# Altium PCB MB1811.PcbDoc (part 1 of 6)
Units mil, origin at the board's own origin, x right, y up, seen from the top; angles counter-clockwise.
Board outline 3480.3 x 4291.34 mil, 4 copper layers (Top Layer, L2_VCC, L3_GND, Bottom Layer), stack 30.59 mil thick; 371 components, 285 nets, 1369 pads, 606 vias.
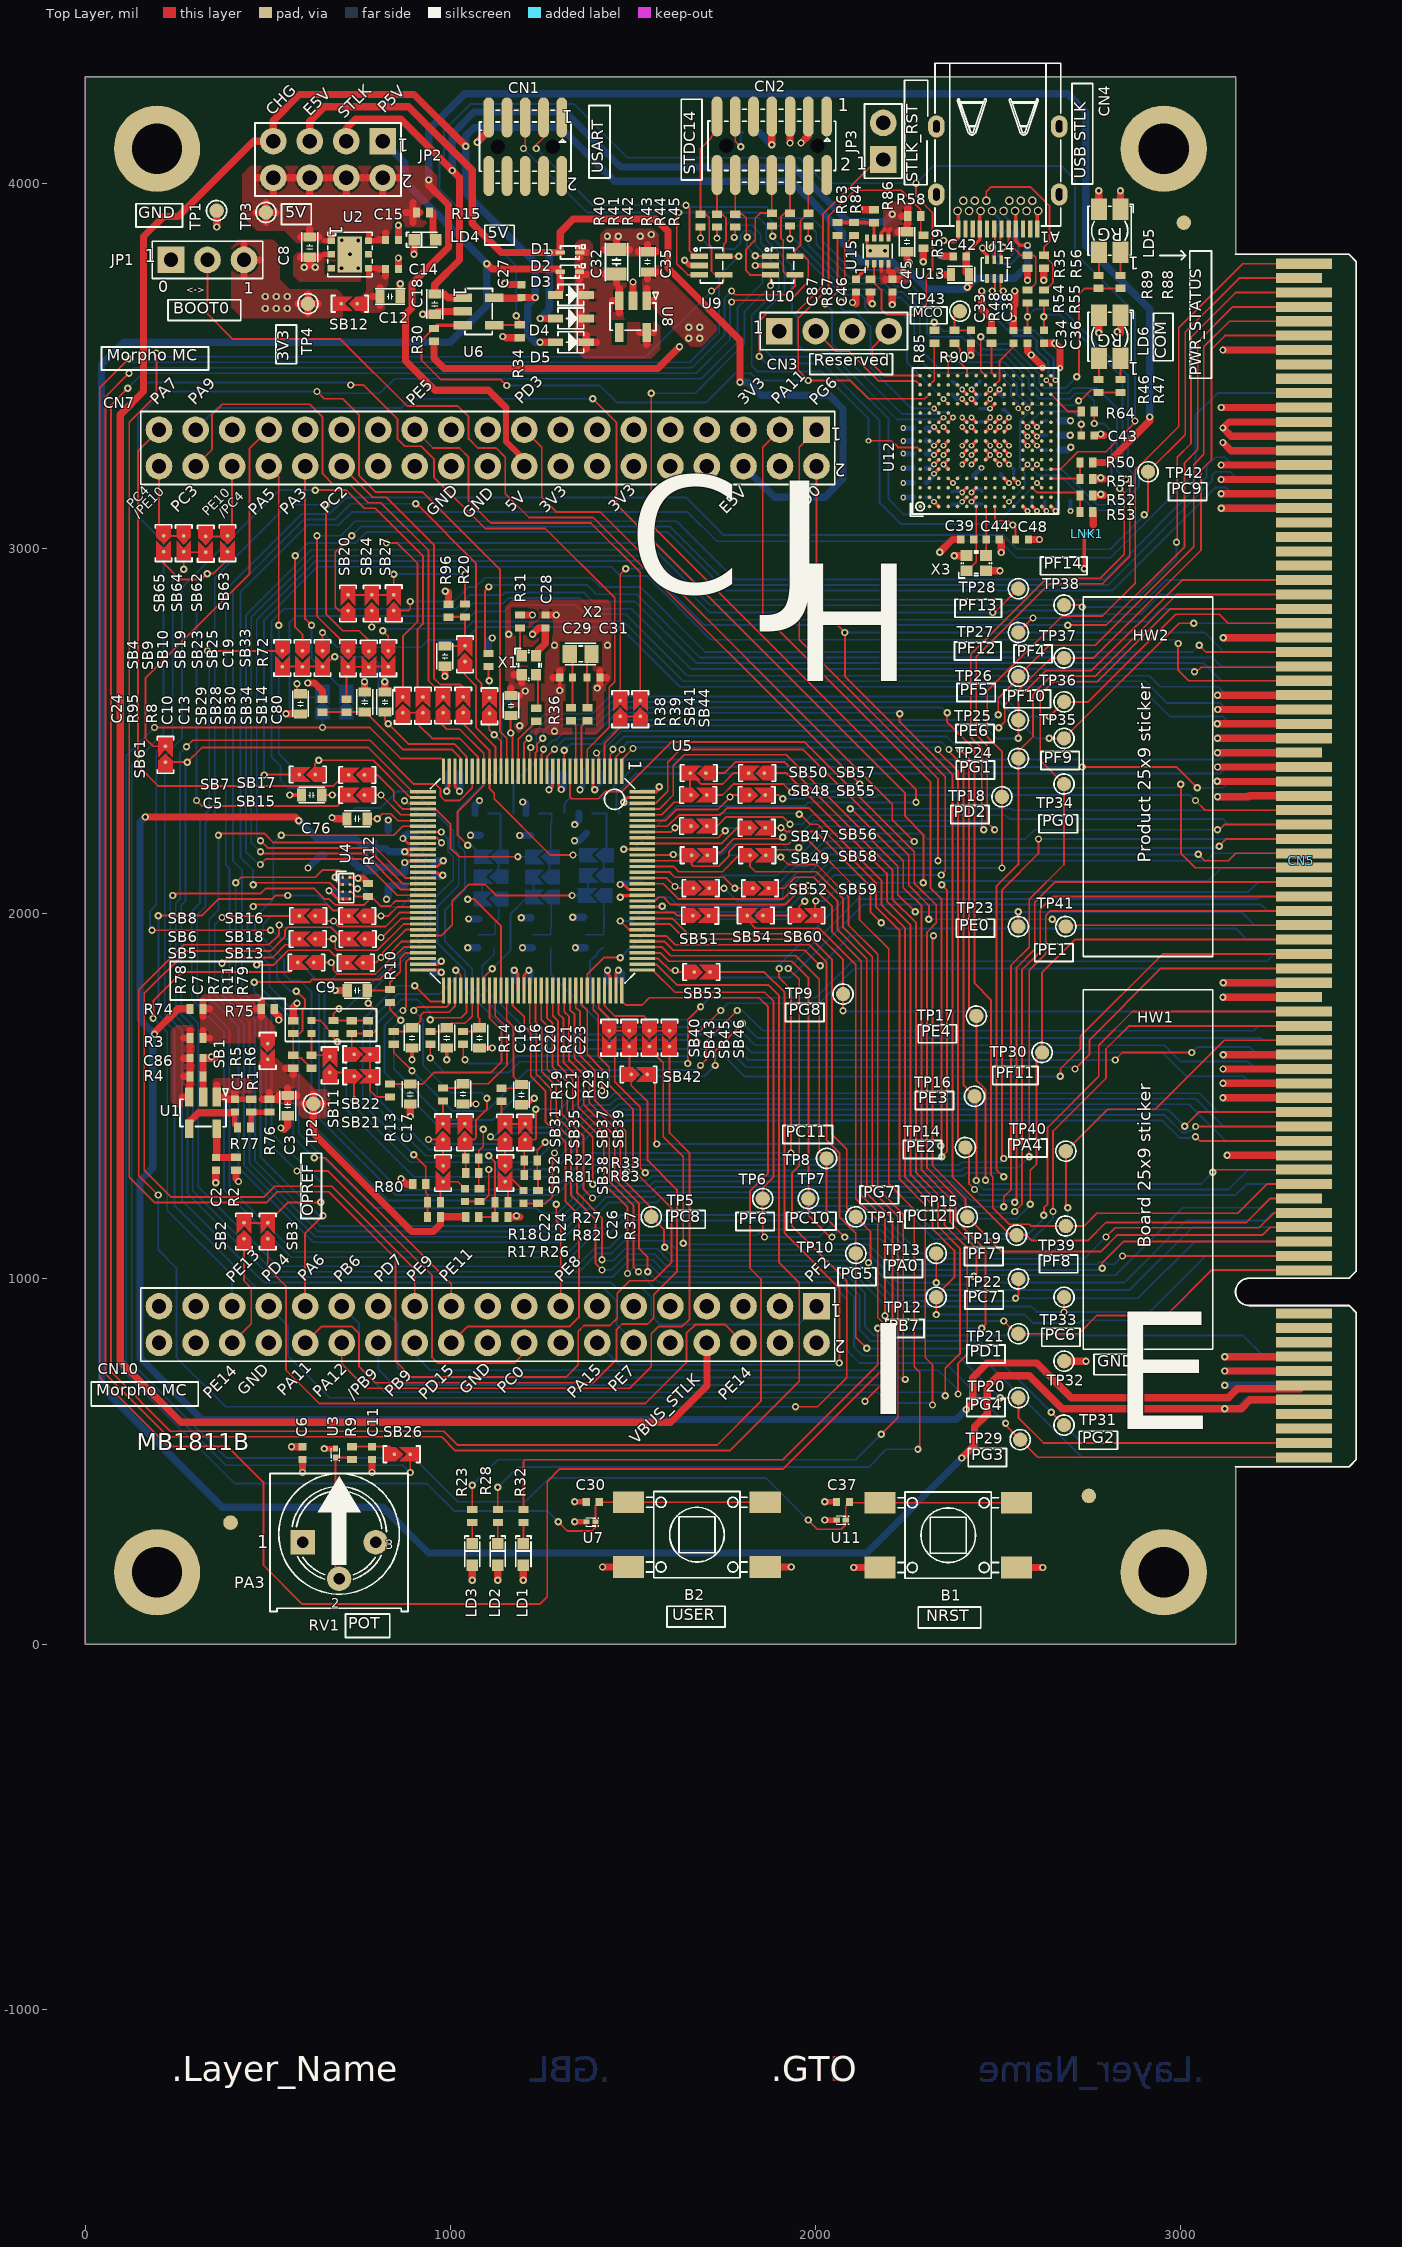
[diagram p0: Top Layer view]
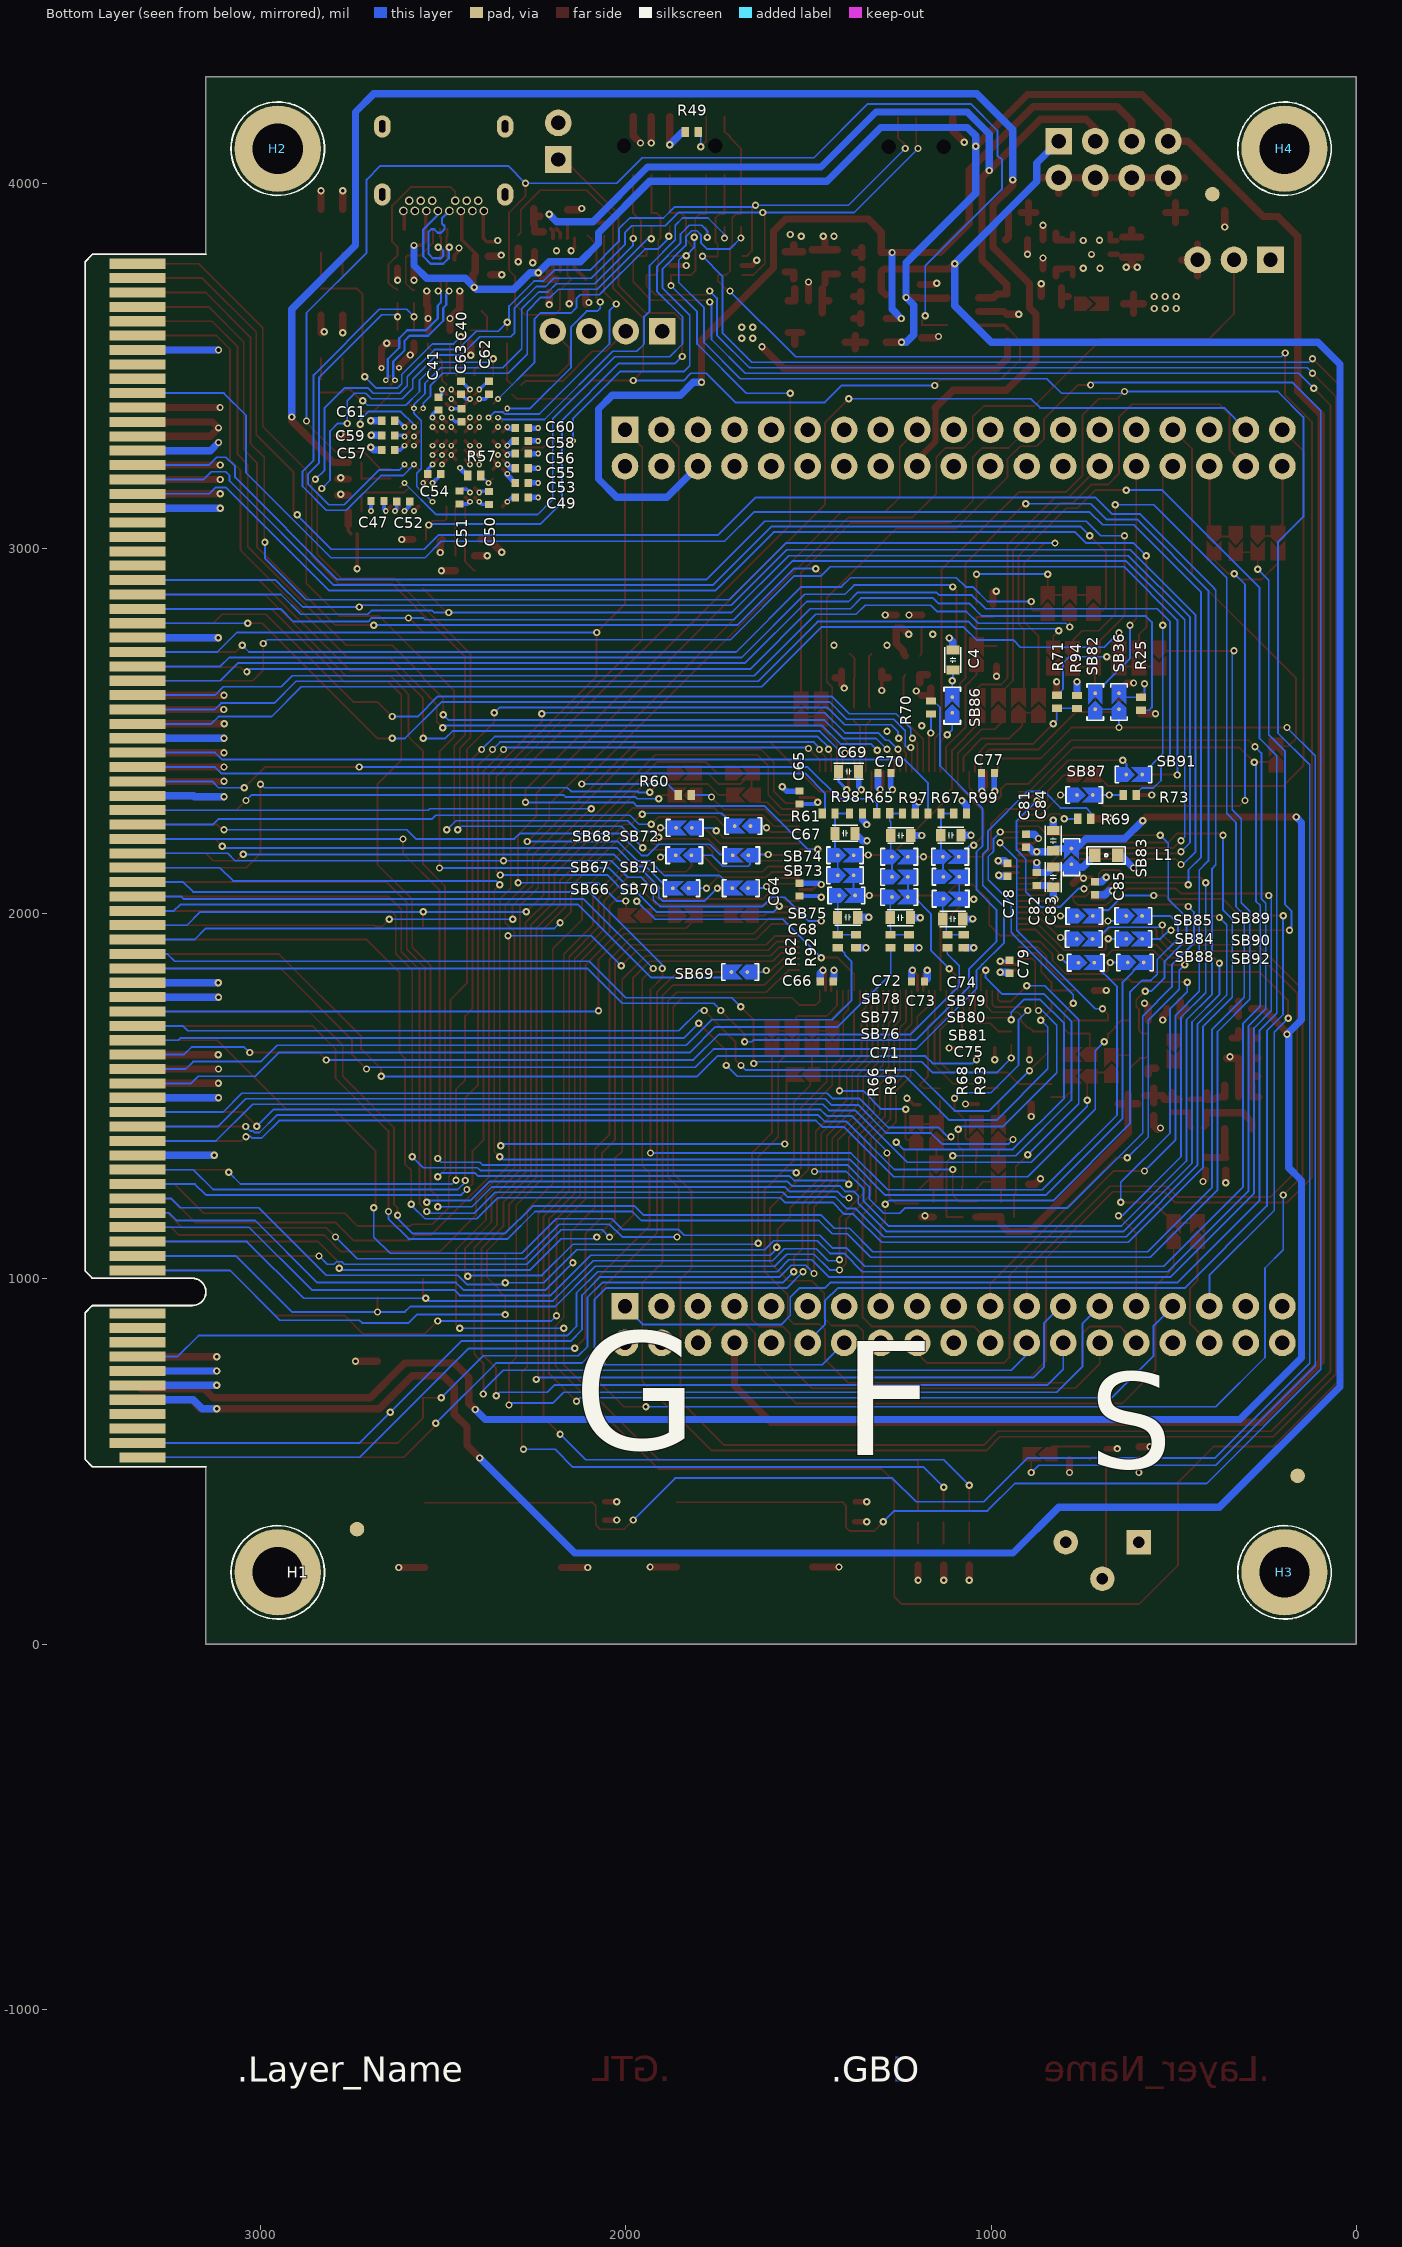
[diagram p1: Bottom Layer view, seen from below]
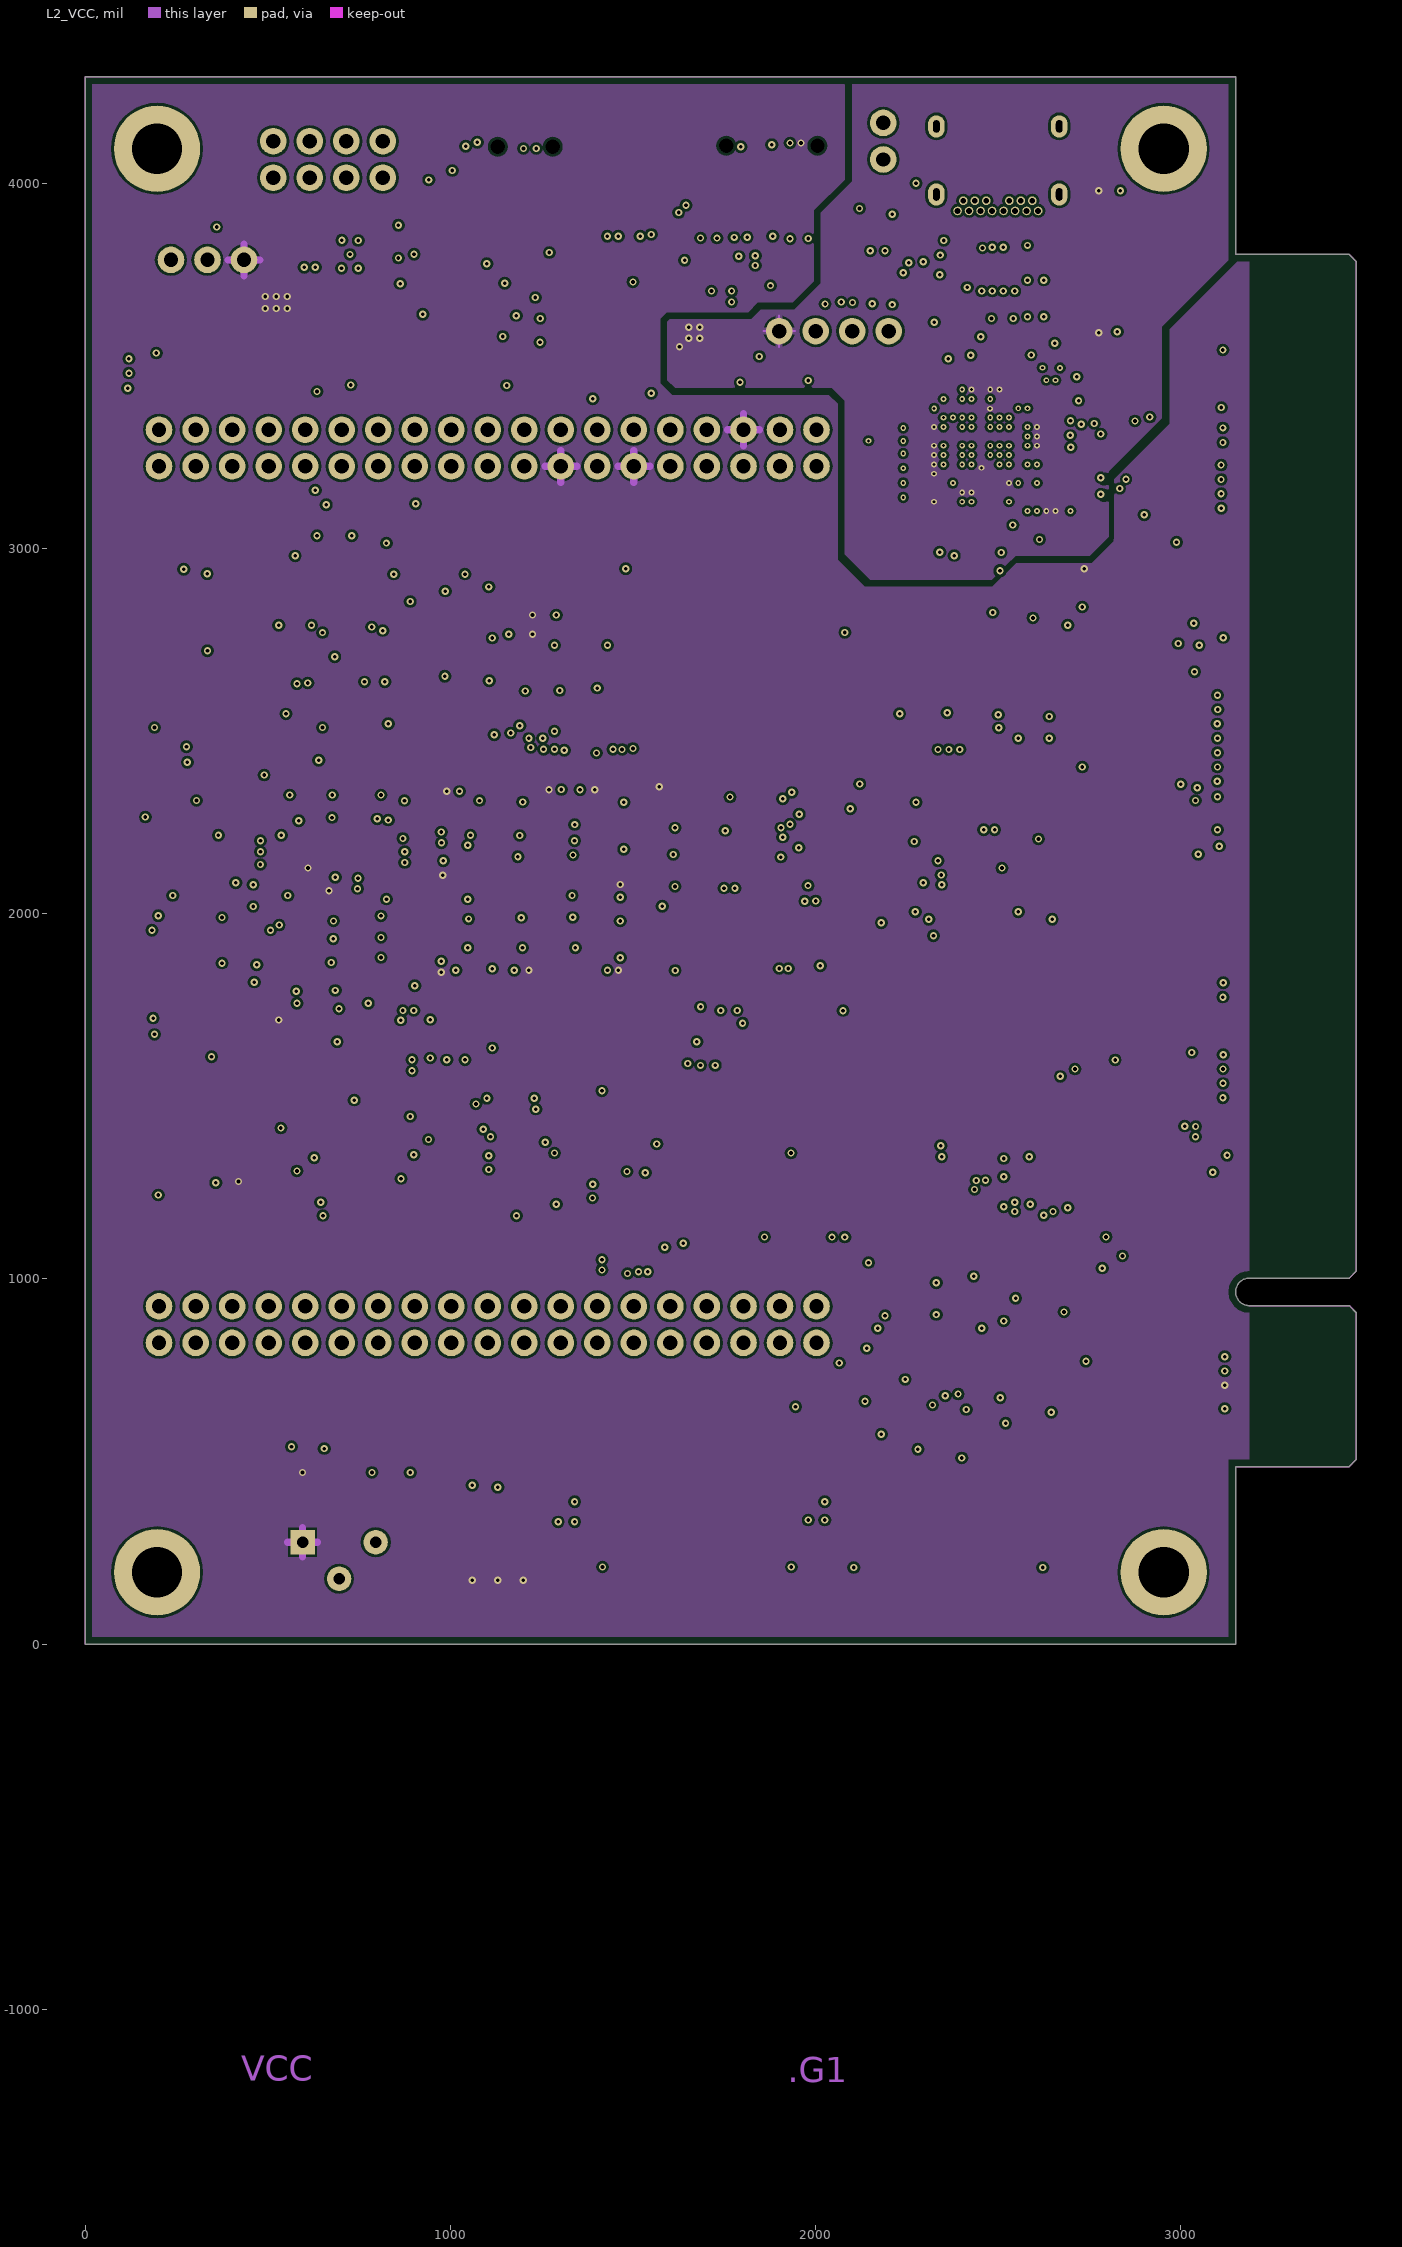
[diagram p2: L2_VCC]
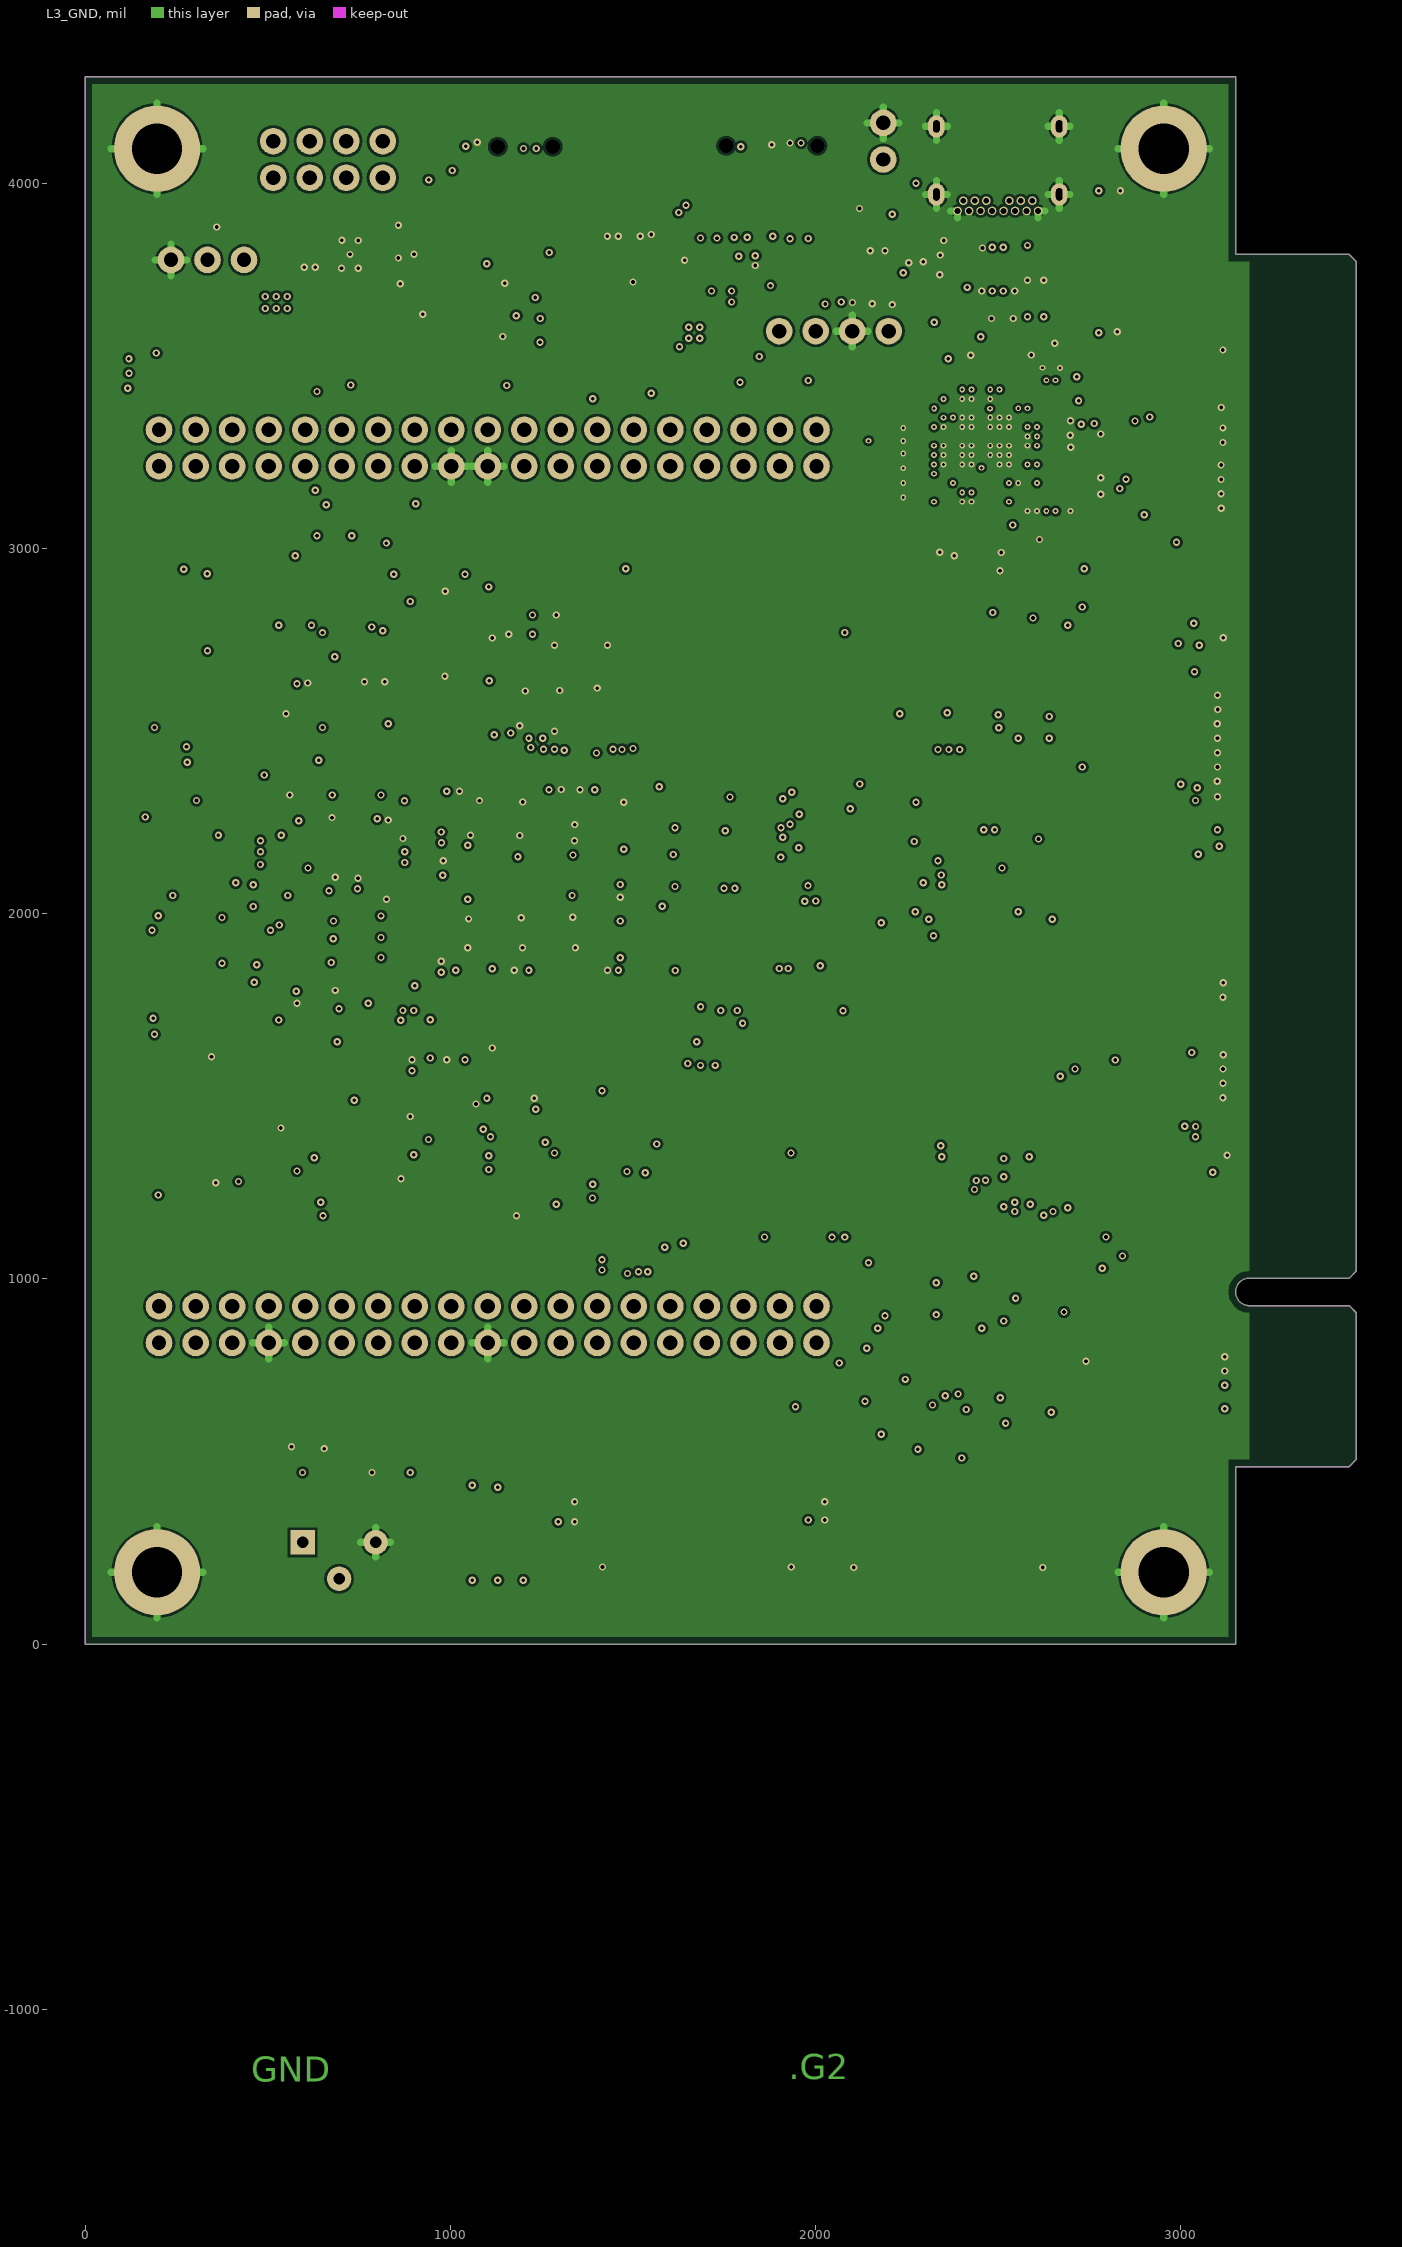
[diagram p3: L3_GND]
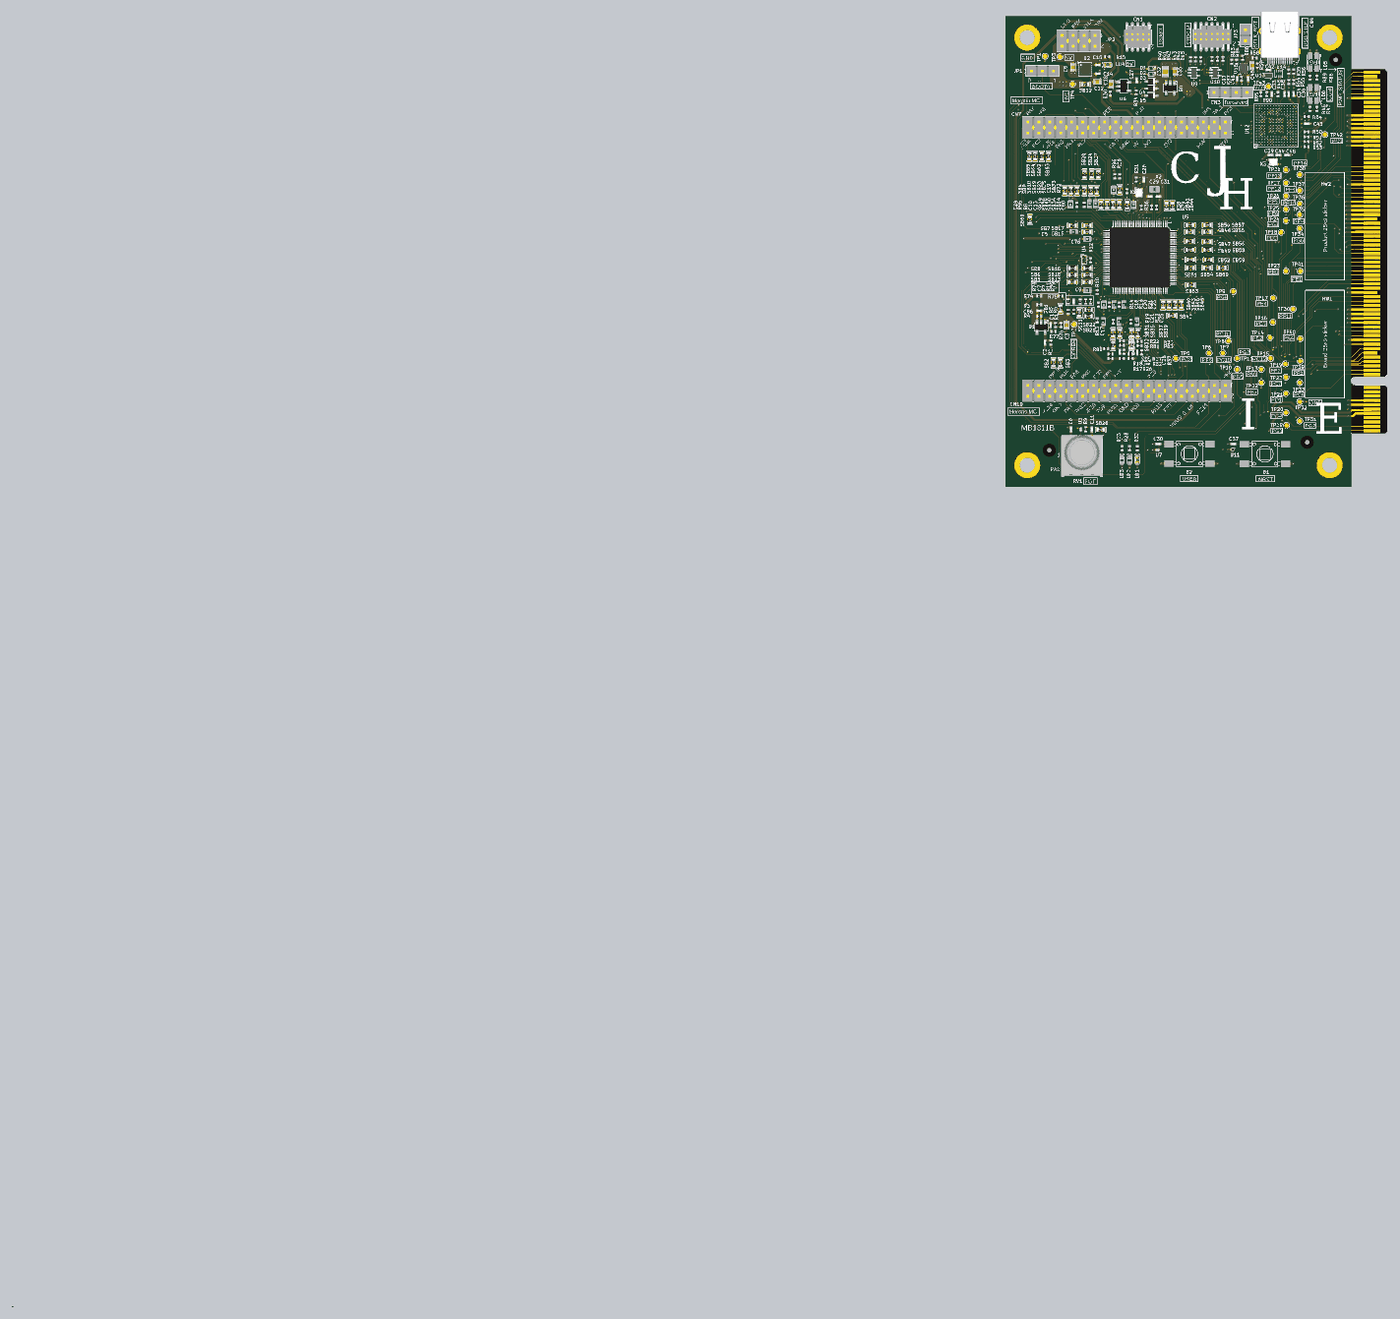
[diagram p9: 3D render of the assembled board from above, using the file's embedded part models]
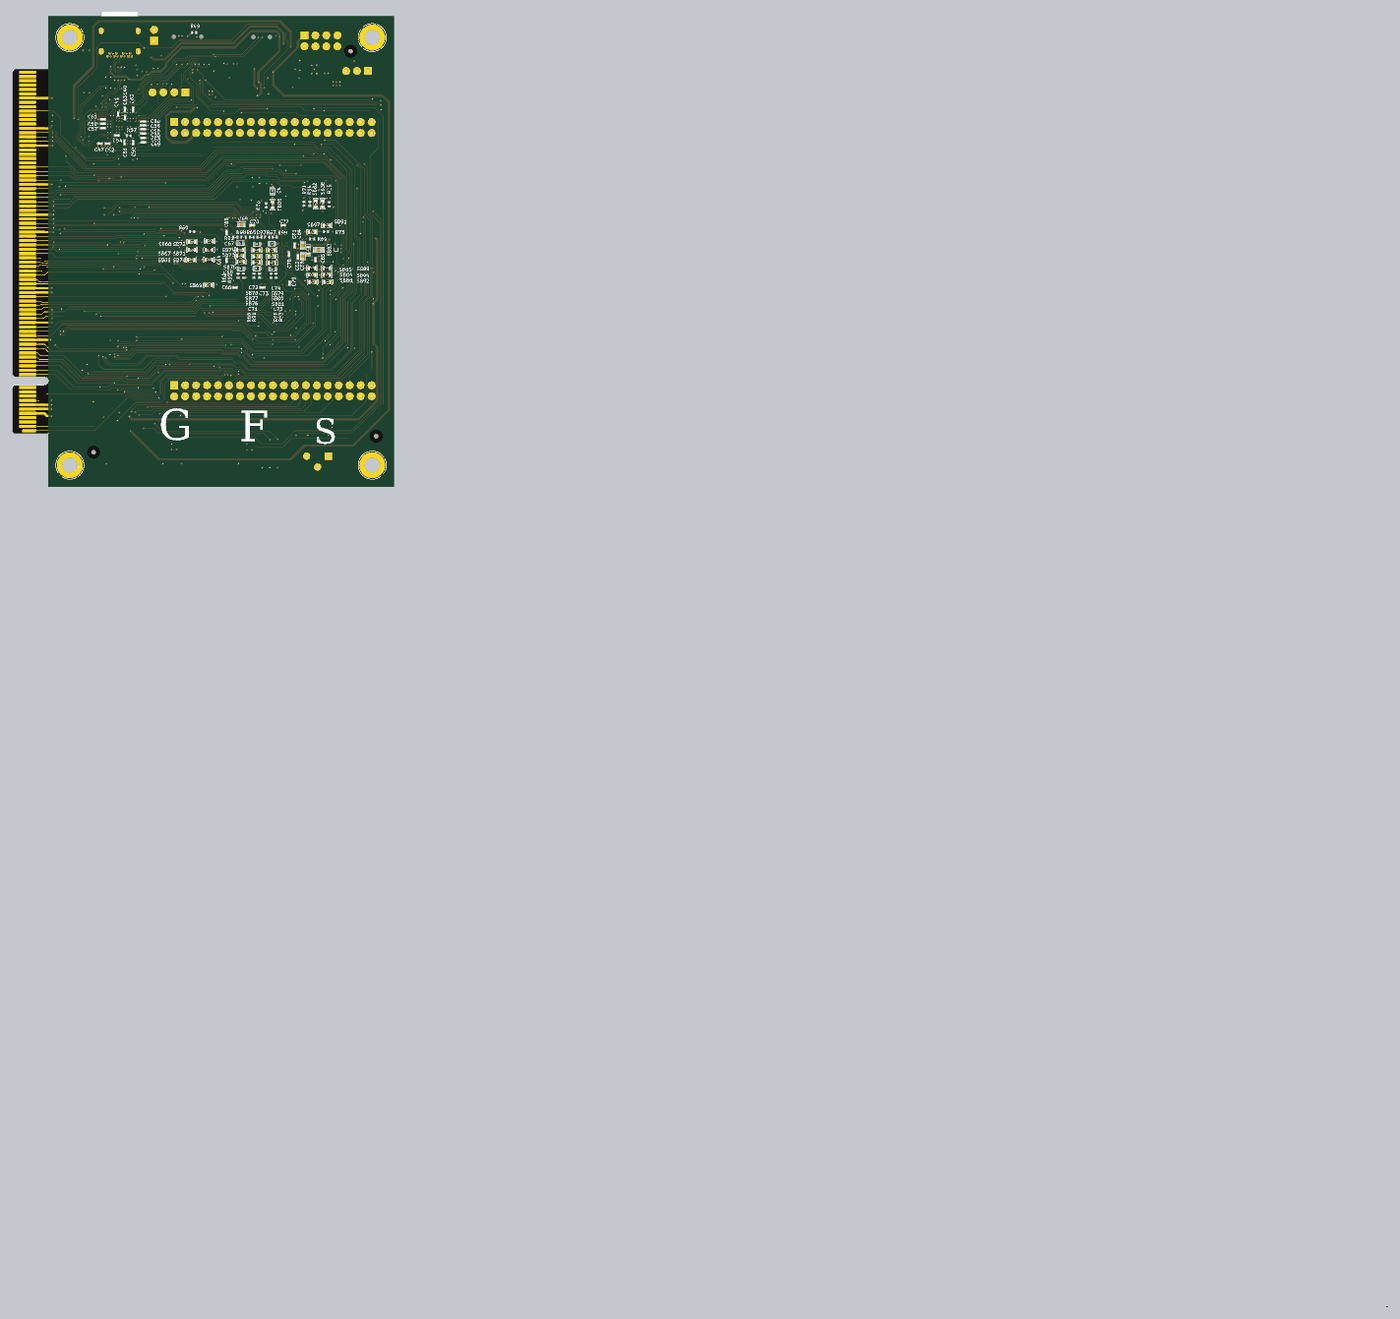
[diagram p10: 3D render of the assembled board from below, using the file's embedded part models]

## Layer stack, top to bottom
Top Solder: solder mask 0.5909, Solder Resist, Dk 3.5
Top Layer: signal copper 1.378
Dielectric 1: core 10, FR-4, Dk 4.2
L2_VCC: signal copper 1.4169
Dielectric 3: prepreg 5, Dk 4.2
L3_GND: signal copper 1.4169
Dielectric 2: core 10, Dk 4.2
Bottom Layer: signal copper 1.378
Bottom Solder: solder mask 0.5909, Solder Resist, Dk 3.5

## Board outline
0,0 3150,0 3150,486.24 3460.61,486.24 3480.3,505.92 3480.3,907.5 3461.6,926.2 3460.61,927.18 3186.99,927.18 cw(c3186.99,964.58) 3186.99,1001.98 3460.61,1001.98 3461.6,1002.97 3480.3,1021.67 3480.3,3785.45 3461.6,3804.15 3460.61,3805.13 3149.59,3805.13 3149.59,4291.34 0,4291.34
cut-out: -9055.13,-7480.3 -9045.13,-7480.3 -9045.13,-7470.3 -9055.13,-7470.3
cut-out: -9055.13,-7480.3 -9045.13,-7480.3 -9045.13,-7470.3 -9055.13,-7470.3

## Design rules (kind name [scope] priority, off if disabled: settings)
Clearance Clearance_USB-1 [InNet('USB_DEV_HS_N') vs InNet('USB_DEV_HS_P')] p1: gap=5 ignorepadtopadclearanceinfootprint=FALSE except(0: Arc-Hole Track-Hole SMDPad-Hole THPad-Hole Via-Hole Fill-Hole Poly-Hole Region-Hole Text-Hole; 7: Arc-Fill Arc-Poly Arc-Region Track-Fill Track-Poly Track-Region THPad-Fill THPad-Poly THPad-Region Via-Fill Via-Poly Via-Region; 8.9: Arc-Arc Arc-Track Track-Track; 10: SMDPad-Fill SMDPad-Poly SMDPad-Region; 15: Fill-Fill Fill-Poly Fill-Region Poly-Poly Poly-Region Region-Region)
Clearance Clearance_USB [InNetClass('USB')] p2: gap=5 ignorepadtopadclearanceinfootprint=FALSE except(0: Arc-Hole Track-Hole SMDPad-Hole THPad-Hole Via-Hole Fill-Hole Poly-Hole Region-Hole Text-Hole; 7: Arc-Fill Arc-Poly Arc-Region Track-Fill Track-Poly Track-Region THPad-Fill THPad-Poly THPad-Region Via-Fill Via-Poly Via-Region; 8.9: Arc-Arc Arc-Track Track-Track; 10: SMDPad-Fill SMDPad-Poly SMDPad-Region; 15: Fill-Fill Fill-Poly Fill-Region Poly-Poly Poly-Region Region-Region)
Clearance Clearance_U1 [WithinRoom('Room_U1')] p3: gap=5 ignorepadtopadclearanceinfootprint=FALSE except(0: Arc-Hole Track-Hole SMDPad-Hole THPad-Hole Via-Hole Fill-Hole Poly-Hole Region-Hole Text-Hole; 7: Arc-Arc Arc-Track Arc-Fill Arc-Poly Arc-Region Track-Track Track-Fill Track-Poly Track-Region THPad-Fill THPad-Poly THPad-Region Via-Fill Via-Poly Via-Region; 10: SMDPad-Fill SMDPad-Poly SMDPad-Region; 15: Fill-Fill Fill-Poly Fill-Region Poly-Poly Poly-Region Region-Region)
Clearance Clearance_U8 [WithinRoom('Room_U8')] p4: gap=5 ignorepadtopadclearanceinfootprint=FALSE except(0: Arc-Hole Track-Hole SMDPad-Hole THPad-Hole Via-Hole Fill-Hole Poly-Hole Region-Hole Text-Hole; 7: Arc-Fill Arc-Poly Arc-Region Track-Fill Track-Poly Track-Region THPad-Fill THPad-Poly THPad-Region Via-Fill Via-Poly Via-Region; 10: SMDPad-Fill SMDPad-Poly SMDPad-Region; 15: Fill-Fill Fill-Poly Fill-Region Poly-Poly Poly-Region Region-Region)
Clearance Clearance_SB [HasFootprint('SOLDER-BRIDGE_R0603-0R')] p5: gap=4 ignorepadtopadclearanceinfootprint=FALSE except(0: Arc-Hole Track-Hole SMDPad-Hole THPad-Hole Via-Hole Fill-Hole Poly-Hole Region-Hole Text-Hole)
Clearance [All] p6: gap=5 ignorepadtopadclearanceinfootprint=FALSE except(0: Arc-Hole Track-Hole SMDPad-Hole THPad-Hole Via-Hole Fill-Hole Poly-Hole Region-Hole Text-Hole; 7: Arc-Fill Arc-Poly Arc-Region Track-Fill Track-Poly Track-Region THPad-Fill THPad-Poly THPad-Region Via-Fill Via-Poly Via-Region; 9.59: SMDPad-Fill SMDPad-Poly SMDPad-Region; 10: Arc-Arc Arc-Track Track-Track; 15: Fill-Fill Fill-Poly Fill-Region Poly-Poly Poly-Region Region-Region)
ComponentClearance [All] p1: gap=7.87 collisioncheckmode=3 verticalgap=7.87 showdistances=FALSE
DiffPairsRouting 90OHM [InDifferentialPairClass('USB')] p1: maxlimit=8.9 minlimit=8.9 mostfreqgap=8.9 substack1={F80C8400-F314-4E3F-8811-031F20A8500E} toplayer_{f80c8400-f314-4e3f-8811-031f20a8500e}_minwidth=15 toplayer_{f80c8400-f314-4e3f-8811-031f20a8500e}_maxwidth=15 toplayer_{f80c8400-f314-4e3f-8811-031f20a8500e}_prefwidth=15 midlayer1_{f80c8400-f314-4e3f-8811-031f20a8500e}_minwidth=15 midlayer1_{f80c8400-f314-4e3f-8811-031f20a8500e}_maxwidth=15 midlayer1_{f80c8400-f314-4e3f-8811-031f20a8500e}_prefwidth=15 midlayer2_{f80c8400-f314-4e3f-8811-031f20a8500e}_minwidth=15 midlayer2_{f80c8400-f314-4e3f-8811-031f20a8500e}_maxwidth=15 midlayer2_{f80c8400-f314-4e3f-8811-031f20a8500e}_prefwidth=15 bottomlayer_{f80c8400-f314-4e3f-8811-031f20a8500e}_minwidth=15 bottomlayer_{f80c8400-f314-4e3f-8811-031f20a8500e}_maxwidth=15 bottomlayer_{f80c8400-f314-4e3f-8811-031f20a8500e}_prefwidth=15 toplayer_minwidth=6.1 toplayer_maxwidth=6.1 toplayer_prefwidth=6.1 midlayer1_minwidth=6.1 midlayer1_maxwidth=6.1 midlayer1_prefwidth=6.1 midlayer2_minwidth=6.1 midlayer2_maxwidth=6.1 midlayer2_prefwidth=6.1 bottomlayer_minwidth=6.1 bottomlayer_maxwidth=6.1 bottomlayer_prefwidth=6.1 substack2={91A0764B-7672-4952-B16E-CA0C359586FD} toplayer_{91a0764b-7672-4952-b16e-ca0c359586fd}_minwidth=15 toplayer_{91a0764b-7672-4952-b16e-ca0c359586fd}_maxwidth=15 toplayer_{91a0764b-7672-4952-b16e-ca0c359586fd}_prefwidth=15 midlayer1_{91a0764b-7672-4952-b16e-ca0c359586fd}_minwidth=15 midlayer1_{91a0764b-7672-4952-b16e-ca0c359586fd}_maxwidth=15 midlayer1_{91a0764b-7672-4952-b16e-ca0c359586fd}_prefwidth=15 midlayer2_{91a0764b-7672-4952-b16e-ca0c359586fd}_minwidth=15 midlayer2_{91a0764b-7672-4952-b16e-ca0c359586fd}_maxwidth=15 midlayer2_{91a0764b-7672-4952-b16e-ca0c359586fd}_prefwidth=15 bottomlayer_{91a0764b-7672-4952-b16e-ca0c359586fd}_minwidth=15 bottomlayer_{91a0764b-7672-4952-b16e-ca0c359586fd}_maxwidth=15 bottomlayer_{91a0764b-7672-4952-b16e-ca0c359586fd}_prefwidth=15 substack3={F9E4DBCF-B49B-4863-836C-BE9749C8D588} toplayer_{f9e4dbcf-b49b-4863-836c-be9749c8d588}_minwidth=15 toplayer_{f9e4dbcf-b49b-4863-836c-be9749c8d588}_maxwidth=15 toplayer_{f9e4dbcf-b49b-4863-836c-be9749c8d588}_prefwidth=15 midlayer1_{f9e4dbcf-b49b-4863-836c-be9749c8d588}_minwidth=15 midlayer1_{f9e4dbcf-b49b-4863-836c-be9749c8d588}_maxwidth=15 midlayer1_{f9e4dbcf-b49b-4863-836c-be9749c8d588}_prefwidth=15 midlayer2_{f9e4dbcf-b49b-4863-836c-be9749c8d588}_minwidth=15 midlayer2_{f9e4dbcf-b49b-4863-836c-be9749c8d588}_maxwidth=15 midlayer2_{f9e4dbcf-b49b-4863-836c-be9749c8d588}_prefwidth=15 bottomlayer_{f9e4dbcf-b49b-4863-836c-be9749c8d588}_minwidth=15 bottomlayer_{f9e4dbcf-b49b-4863-836c-be9749c8d588}_maxwidth=15 bottomlayer_{f9e4dbcf-b49b-4863-836c-be9749c8d588}_prefwidth=15 maxuncoupledlength=500
DiffPairsRouting [All] p2: maxlimit=10 minlimit=10 mostfreqgap=10 substack1={F80C8400-F314-4E3F-8811-031F20A8500E} toplayer_{f80c8400-f314-4e3f-8811-031f20a8500e}_minwidth=15 toplayer_{f80c8400-f314-4e3f-8811-031f20a8500e}_maxwidth=15 toplayer_{f80c8400-f314-4e3f-8811-031f20a8500e}_prefwidth=15 midlayer1_{f80c8400-f314-4e3f-8811-031f20a8500e}_minwidth=15 midlayer1_{f80c8400-f314-4e3f-8811-031f20a8500e}_maxwidth=15 midlayer1_{f80c8400-f314-4e3f-8811-031f20a8500e}_prefwidth=15 midlayer2_{f80c8400-f314-4e3f-8811-031f20a8500e}_minwidth=15 midlayer2_{f80c8400-f314-4e3f-8811-031f20a8500e}_maxwidth=15 midlayer2_{f80c8400-f314-4e3f-8811-031f20a8500e}_prefwidth=15 bottomlayer_{f80c8400-f314-4e3f-8811-031f20a8500e}_minwidth=15 bottomlayer_{f80c8400-f314-4e3f-8811-031f20a8500e}_maxwidth=15 bottomlayer_{f80c8400-f314-4e3f-8811-031f20a8500e}_prefwidth=15 toplayer_minwidth=15 toplayer_maxwidth=15 toplayer_prefwidth=15 midlayer1_minwidth=15 midlayer1_maxwidth=15 midlayer1_prefwidth=15 midlayer2_minwidth=15 midlayer2_maxwidth=15 midlayer2_prefwidth=15 bottomlayer_minwidth=15 bottomlayer_maxwidth=15 bottomlayer_prefwidth=15 substack2={91A0764B-7672-4952-B16E-CA0C359586FD} toplayer_{91a0764b-7672-4952-b16e-ca0c359586fd}_minwidth=15 toplayer_{91a0764b-7672-4952-b16e-ca0c359586fd}_maxwidth=15 toplayer_{91a0764b-7672-4952-b16e-ca0c359586fd}_prefwidth=15 midlayer1_{91a0764b-7672-4952-b16e-ca0c359586fd}_minwidth=15 midlayer1_{91a0764b-7672-4952-b16e-ca0c359586fd}_maxwidth=15 midlayer1_{91a0764b-7672-4952-b16e-ca0c359586fd}_prefwidth=15 midlayer2_{91a0764b-7672-4952-b16e-ca0c359586fd}_minwidth=15 midlayer2_{91a0764b-7672-4952-b16e-ca0c359586fd}_maxwidth=15 midlayer2_{91a0764b-7672-4952-b16e-ca0c359586fd}_prefwidth=15 bottomlayer_{91a0764b-7672-4952-b16e-ca0c359586fd}_minwidth=15 bottomlayer_{91a0764b-7672-4952-b16e-ca0c359586fd}_maxwidth=15 bottomlayer_{91a0764b-7672-4952-b16e-ca0c359586fd}_prefwidth=15 substack3={F9E4DBCF-B49B-4863-836C-BE9749C8D588} toplayer_{f9e4dbcf-b49b-4863-836c-be9749c8d588}_minwidth=15 toplayer_{f9e4dbcf-b49b-4863-836c-be9749c8d588}_maxwidth=15 toplayer_{f9e4dbcf-b49b-4863-836c-be9749c8d588}_prefwidth=15 midlayer1_{f9e4dbcf-b49b-4863-836c-be9749c8d588}_minwidth=15 midlayer1_{f9e4dbcf-b49b-4863-836c-be9749c8d588}_maxwidth=15 midlayer1_{f9e4dbcf-b49b-4863-836c-be9749c8d588}_prefwidth=15 midlayer2_{f9e4dbcf-b49b-4863-836c-be9749c8d588}_minwidth=15 midlayer2_{f9e4dbcf-b49b-4863-836c-be9749c8d588}_maxwidth=15 midlayer2_{f9e4dbcf-b49b-4863-836c-be9749c8d588}_prefwidth=15 bottomlayer_{f9e4dbcf-b49b-4863-836c-be9749c8d588}_minwidth=15 bottomlayer_{f9e4dbcf-b49b-4863-836c-be9749c8d588}_maxwidth=15 bottomlayer_{f9e4dbcf-b49b-4863-836c-be9749c8d588}_prefwidth=15 maxuncoupledlength=500
HoleSize [All] p1: absolutevalues=TRUE maxlimit=393.7 minlimit=1 maxpercent=80.000 minpercent=20.000
MaxMinImpedance "Schematic Impedance Constraint_6" [InNet('STLK_USB_P')] p1: minimum=85.00 maximum=95.00
MaxMinImpedance "Schematic Impedance Constraint_5" [InNet('STLK_USB_CN_N')] p2: minimum=85.00 maximum=95.00
MaxMinImpedance "Schematic Impedance Constraint_4" [InNet('STLK_USB_CN_P')] p3: minimum=85.00 maximum=95.00
MaxMinImpedance "Schematic Impedance Constraint_3" [InNet('STLK_USB_N')] p4: minimum=85.00 maximum=95.00
MinimumSolderMaskSliver [All] p1: minsoldermaskwidth=0.5
PlaneConnect [All] p1: planeconnectstyle=Relief reliefexpansion=20 reliefentries=4 reliefconductorwidth=10 reliefairgap=6
PolygonConnect PolygonConnect_via [IsVia] p1: connectstyle=Direct reliefconductorwidth=10 reliefentries=4 polygonreliefangle="90 Angle" airgapwidth=10
PolygonConnect [All] p2: connectstyle=Relief reliefconductorwidth=20 reliefentries=4 polygonreliefangle="90 Angle" airgapwidth=6
RoomDefinition Room_U1 [InComponentClass('Components Class 1')] p1: confinementstyle=ConfineIn formatcopy=TRUE lockcomponents=FALSE outline 940,2457 1548,2457 1584,2421 1583,2420 1583,1794 1519.02,1730.02 926.98,1730.02 858,1799 858,2343 866,2351 951,2351 986,2316 986,1885 1010,1861 1434,1861 1451,1878 1451,2304 1433,2322 993,2322 952,2363 916,2363 916,2429 914,2431
RoomDefinition Room_U8 [InComponentClass('Components Class 2')] p2: confinementstyle=ConfineIn formatcopy=TRUE lockcomponents=FALSE outline 2251.63,3503.75 2678.63,3503.75 2678.63,3076.75 2251.63,3076.75
RoutingVias [All] p1: holewidth=8 width=15 viastyle="Through Hole" minholewidth=6 minwidth=12 maxholewidth=12 maxwidth=20
SilkToSilkClearance [All] p1: silktosilkclearance=0.5
SilkToSolderMaskClearance [IsPad] p1: minsilkscreentomaskgap=0.5 clearancetoexposedcopper=TRUE
SolderMaskExpansion [All] p1: expansion=4 istentingtop=FALSE
Width [All] p1: maxlimit=40 minlimit=5 preferedwidth=5 substack1={F80C8400-F314-4E3F-8811-031F20A8500E} substack2={91A0764B-7672-4952-B16E-CA0C359586FD} substack3={F9E4DBCF-B49B-4863-836C-BE9749C8D588}
23 further rules are at their usual default settings.

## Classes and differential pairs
net class USB: STLK_USB_CN_N STLK_USB_CN_P STLK_USB_N STLK_USB_P
component class U_STLINK_V3EC: C18 C27 C32 C33 C34 C35 C36 C38 C39 C40 C41 C42 C43 C44 C45 C46 C47 C48 C49 C50 C51 C52 C53 C54 C55 C56 C57 C58 C59 C60 C61 C62 C63 C87 CN1 CN2 CN3 CN4 D1 D2 D3 D4 D5 JP3 LD5 LD6 LNK1 R30 R34 R35 R40 R41 R42 R43 R44 R45 R46 R47 R48 R49 R50 R51 R52 R53 R54 R55 R56 R57 R58 R59 R63 R64 R84 R85 R86 R87 R88 R89 R90 TP43 U6 U8 U9 U10 U12 U13 U14 U15 X3
component class U_Power: C1 C2 C3 C8 C12 C14 C15 C64 C65 C66 C69 C70 C73 C77 C78 C79 C81 C82 C83 C84 C86 HW4 JP2 L1 LD4 R1 R2 R3 R4 R15 R74 R75 R76 R77 SB1 SB12 SB83 TP1 TP2 TP3 TP4 TP32 U1 U2
component class U_Morpho_MC: CN7 CN10 SB2 SB3 SB42 SB50 SB57 SB62 SB63 SB64 SB65
component class U_Mechanical: H1 H2 H3 H4 HW1 HW2
component class U_MCU: B1 B2 C6 C7 C11 C17 C21 C22 C25 C26 C28 C29 C30 C31 C37 C85 HW3 JP1 LD1 LD2 LD3 R5 R6 R7 R9 R11 R12 R13 R17 R18 R19 R22 R23 R24 R26 R27 R28 R29 R31 R32 R33 R36 R37 R38 R39 R60 R78 R79 R80 R81 R82 R83 RV1 SB5 SB6 SB7 SB8 SB11 SB13 SB14 SB15 SB16 SB17 SB18 SB21 SB22 SB26 SB28 SB29 SB30 SB31 SB32 SB33 SB34 SB35 SB36 SB37 SB38 SB39 SB40 SB41 SB43 SB44 SB45 SB46 SB47 SB48 SB49 SB51 SB52 SB53 SB54 SB55 SB56 SB58 SB59 SB60 SB61 SB66 SB67 SB68 SB69 SB70 SB71 SB72 SB82 SB84 SB85 SB86 SB87 SB88 SB89 SB90 SB91 SB92 TP5 TP6 TP7 TP8 TP9 TP10 TP11 TP12 TP13 TP14 TP15 TP16 TP17 TP18 TP19 TP20 TP21 TP22 TP23 TP24 TP25 TP26 TP27 TP28 TP29 TP30 TP31 TP33 TP34 TP35 TP36 TP37 TP38 TP39 TP40 TP41 TP42 U3 U4 U5 U7 U11 X1 X2
component class U_MC_Connector_V2: C4 C5 C9 C10 C13 C16 C19 C20 C23 C24 C67 C68 C71 C72 C74 C75 C76 C80 CN5 R8 R10 R14 R16 R20 R21 R25 R61 R62 R65 R66 R67 R68 R69 R70 R71 R72 R73 R91 R92 R93 R94 R95 R96 R97 R98 R99 SB4 SB9 SB10 SB19 SB20 SB23 SB24 SB25 SB27 SB73 SB74 SB75 SB76 SB77 SB78 SB79 SB80 SB81
differential pair STLK_USB: +STLK_USB_P -STLK_USB_N
differential pair STLK_USB_CN: +STLK_USB_CN_P -STLK_USB_CN_N

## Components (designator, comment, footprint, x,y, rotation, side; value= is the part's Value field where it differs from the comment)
B1 "SW_PUSH_SMD" SWI_WEALTHMETAL_TD-0341_4P_BLACK 2362.98,298.59 r90 top value=SWITCH
B2 "SW_PUSH_SMD" SWI_WEALTHMETAL_TD-0341_4P_BLUE 1674.99,300.01 r90 top value=SWITCH
C1 "Capacitor" C0402 409.87,1474.7 r90 top value=1nF
C2 "Capacitor" C0402 357.87,1314.99 r90 top value=100nF
C3 "Capacitor" C0603 554.87,1474.69 r90 top value=2.2uF
C4 "Capacitor" C0603_H0P8 1104.56,2694.58 r270 bottom value=2.2nF
C5 "Capacitor" C0603_H0P8 619.99,2325.01 r0 top value=2.2nF
C6 "Capacitor" C0402 595.27,523.32 r270 top value=100nF
C7 "Capacitor" C0402 619.87,1689.7 r270 top value=1nF
C8 "Capacitor" C0603 614.99,3825.01 r90 top value=1uF
C9 "Capacitor" C0603_H0P8 744.98,1790.01 r0 top value=2.2nF
C10 "Capacitor" C0603_H0P8 765.66,2579.69 r270 top value=2.2nF
C11 "Capacitor" C0402 785.27,523.32 r90 top value=100nF
C12 "Capacitor" C0603 834.99,3690.01 r180 top value=1uF
C13 "Capacitor" C0603_H0P8 820.66,2579.68 r270 top value=2.2nF
C14 "Capacitor" C0402 840,3765.01 r180 top value=100nF
C15 "Capacitor" C0402 840,3845.01 r180 top value=100nF
C16 "Capacitor" C0603_H0P8 894.99,1660.01 r90 top value=2.2nF
C17 "Capacitor" C0603_H0P8 890,1506.23 r90 top value=2.2nF
C18 "Capacitor" C0603 957.11,3668.94 r90 top value=10uF
C19 "Capacitor" C0603_H0P8 984.99,2705 r90 top value=2.2nF
C20 "Capacitor" C0603_H0P8 989.99,1660.01 r90 top value=2.2nF
C21 "Capacitor" C0603_H0P8 1034.71,1506.7 r90 top value=2.2nF
C22 "Capacitor" C0402 1039.87,1229.7 r90 top value=1nF
C23 "Capacitor" C0603_H0P8 1079.99,1660.01 r90 top value=2.2nF
C24 "Capacitor" C0603_H0P8 589.87,2574.7 r90 top value=2.2nF
C25 "Capacitor" C0603_H0P8 1194.83,1504.53 r90 top value=2.2nF
C26 "Capacitor" C0402 1199.87,1224.7 r90 top value=1nF
C27 "Capacitor" C0402 1194.87,3704.69 r270 top value=100nF
C28 "Capacitor" C0402 1259.99,2800 r270 top value=100nF
C29 "Capacitor" C0402 1316.72,2646.29 r0 top value=5.6pF
C30 "Capacitor" C0402 1389.99,390 r0 top value=100nF
C31 "Capacitor" C0402 1391.72,2646.29 r180 top value=5.6pF
C32 "Capacitor" C0805 1454.87,3784.69 r270 top value=2.2uF
C33 "Capacitor" C0402 2424.87,3579.7 r90 top value=20pF
C34 "Capacitor" C0402 2579.87,3579.7 r270 top value=10nF
C35 "Capacitor" C0603 1539.87,3784.7 r270 top value=10uF
C36 "Capacitor" C0402 2624.87,3579.7 r270 top value=10nF
C37 "Capacitor" C0402 2074.99,390 r0 top value=100nF
C38 "Capacitor" C0402 2541.35,3579.12 r270 top value=2.2uF
C39 "Capacitor" C0402 2414.87,3024.7 r180 top value=2.7pF
C40 "Capacitor" C0402 2450.87,3439.69 r270 bottom value=100nF
C41 "Capacitor" C0402 2512.27,3396.59 r270 bottom value=100nF
C42 "Capacitor" C0402 2394.88,3799.7 r180 top value=100pF
C43 "Capacitor" C0402 2744.87,3309.7 r180 top value=2.2uF
C44 "Capacitor" C0402 2484.87,3024.7 r180 top value=2.7pF
C45 "Capacitor" C0603 2249.87,3839.7 r90 top value=10uF
C46 "Capacitor" C0402 2209.87,3719.7 r90 top value=100nF
C47 "Capacitor" C0402 2679.88,3129.7 r0 bottom value=100nF
C48 "Capacitor" C0402 2564.87,3024.7 r180 top value=100nF
C49 "Capacitor" C0402 2284.88,3139.7 r180 bottom value=100nF
C50 "Capacitor" C0402 2374.7,3138.11 r270 bottom value=100nF
C51 "Capacitor" C0402 2455.18,3139.59 r270 bottom value=100nF
C52 "Capacitor" C0402 2609.7,3129.12 r180 bottom value=100nF
C53 "Capacitor" C0402 2285.2,3179.58 r180 bottom value=100nF
C54 "Capacitor" C0402 2524.7,3204.12 r0 bottom value=100nF
C55 "Capacitor" C0402 2285.2,3219.58 r180 bottom value=100nF
C56 "Capacitor" C0402 2285.2,3259.58 r180 bottom value=100nF
C57 "Capacitor" C0402 2650.18,3269.58 r0 bottom value=100nF
C58 "Capacitor" C0402 2285.2,3294.58 r180 bottom value=100nF
C59 "Capacitor" C0402 2650.18,3309.58 r0 bottom value=100nF
C60 "Capacitor" C0402 2284.88,3329.7 r180 bottom value=100nF
C61 "Capacitor" C0402 2650.18,3349.58 r0 bottom value=100nF
C62 "Capacitor" C0402 2374.87,3439.7 r90 bottom value=2.2uF
C63 "Capacitor" C0402 2449.87,3364.69 r270 bottom value=100nF
C64 "Capacitor" C0402 1524.99,2066.07 r90 bottom value=100nF
C65 "Capacitor" C0402 1524.99,2318.03 r90 bottom value=100nF
C66 "Capacitor" C0402 1450,1815.01 r0 bottom value=100nF
C67 "Capacitor" C0603_H0P8 1399.99,2220 r0 bottom value=2.2nF
C68 "Capacitor" C0603_H0P8 1392.55,1990 r0 bottom value=2.2nF
C69 "Capacitor" C0603 1390.34,2389.69 r0 bottom value=4.7uF
C70 "Capacitor" C0402 1291.92,2384.69 r180 bottom value=100nF
C71 "Capacitor" C0603_H0P8 1248.45,1989.28 r0 bottom value=2.2nF
C72 "Capacitor" C0603_H0P8 1247.24,2214.11 r0 bottom value=2.2nF
C73 "Capacitor" C0402 1199.99,1815.01 r0 bottom value=100nF
C74 "Capacitor" C0603_H0P8 1109.99,2215.01 r0 bottom value=2.2nF
C75 "Capacitor" C0603_H0P8 1104.99,1985.76 r0 bottom value=2.2nF
C76 "Capacitor" C0603_H0P8 744.87,2259.7 r0 top value=2.2nF
C77 "Capacitor" C0402 1008.46,2384.69 r180 bottom value=100nF
C78 "Capacitor" C0402 954.99,2120.01 r270 bottom value=100nF
C79 "Capacitor" C0402 949.99,1855.01 r270 bottom value=100nF
C80 "Capacitor" C0603_H0P8 1166,2570 r270 top value=2.2nF
C81 "Capacitor" C0402 904.99,2200 r270 bottom value=100nF
C82 "Capacitor" C0402 874.99,2095.01 r90 bottom value=10nF
C83 "Capacitor" C0603 829.99,2100.01 r90 bottom value=1uF
C84 "Capacitor" C0603 829.99,2200.01 r270 bottom value=1uF
C85 "Capacitor" C0402 714.99,2070 r270 bottom value=100nF
C86 "Capacitor" C0402 304.88,1604.7 r180 top value=100nF
C87 "Capacitor" C0402 2109.87,3719.7 r90 top value=10nF
CN1 "Header 5x2" CON_SAMTEC_FTSH-105-01-L-DV-K 1204.99,4100 r180 top
CN2 "Header 7x2" CON_SAMTEC_FTSH-107-01-L-DV-K-A 1879.99,4102.49 r180 top value="Header 7X2"
CN3 "Header 4x1" CON_SAMTEC_TSW-104-07-G-S 2049.99,3595 r0 top
CN4 "USB_TYPE_C_Receptacle_317JD24BZTF3K3C3" CON_USB-TYPEC_COXOC_317JD24BZTF3K3C3 2498.73,4291.33 r180 top locked value=USB_C_317JD24BZTF3K3C3
CN5 "PCIE-Gold Finger-X16" CON_BOARD_GOLDFINGER_PCI_EXPRESS_X16 3336.8,964.58 r90 top value=N/A
CN7 "Header 19x2" CON_SAMTEC_TSW-119-09-X-D 1102.37,3275 r180 top locked
CN10 "Header 19x2" CON_SAMTEC_TSW-119-09-X-D 1102.37,875 r180 top locked
D1 "SCHOTTKY_1A_2K" DIO_SOD523_1A_2K 1327.18,3810.08 r0 top value=BAT54KFILM
D2 "SCHOTTKY_1A_2K" DIO_SOD523_1A_2K 1327,3758 r0 top value=BAT54KFILM
D3 "SCHOTTKY_1A_2K" DIO_SOD323_1A_2K 1330,3694 r0 top value=BAT20JFILM
D4 "SCHOTTKY_1A_2K" DIO_SOD323_1A_2K 1329.88,3629.7 r0 top value=BAT20JFILM
D5 "SCHOTTKY_1A_2K" DIO_SOD323_1A_2K 1329.88,3564.7 r0 top value=BAT20JFILM
H1 "POSITION HOLE" PTH_M1261-3005-N_3P5X6_M3_H14 2952.74,196.86 r180 bottom locked
H2 "POSITION HOLE" PTH_M1261-3005-N_3P5X6_M3_H14 2952.74,4094.49 r180 bottom locked
H3 "POSITION HOLE" PTH_M1261-3005-N_3P5X6_M3_H14 196.84,196.86 r180 bottom locked
H4 "POSITION HOLE" PTH_M1261-3005-N_3P5X6_M3_H14 196.84,4094.49 r180 bottom
HW1 "STICKER_BOARD" STICKER_BOARD_25X9 2909.98,1300.02 r90 top locked value="Sticker board"
HW2 "STICKER_PRODUCT" STICKER_PRODUCT_25X9 2909.98,2375.02 r90 top locked value="Sticker product"
JP1 "Jumper_Header 3x1 Fitted 1-2" CON_SAMTEC_TSW-103-07-F-S 334.99,3790 r0 top value="Header 3x1"
JP2 "Jumper_Header 4x2 Fitted 1-2" CON_SAMTEC_TSW-104-07-X-D 664.99,4065.01 r180 top value="Header 4x2"
JP3 "Jumper_Header 2x1" CON_SAMTEC_TSW-102-07-G-S 2184.99,4115.01 r90 top value="Header 2x1"
L1 "BEAD" L0603 684.99,2160.01 r180 bottom value="600R @ 100MHz"
LD1 "LED_green" LED_0603_OSRAM_LG-Q396-PS-35_GREEN_1A2K_H0P4 1199.83,246.14 r90 top value=GREEN
LD2 "LED_red" LED_0603_VISHAY_VLMS1300-GS08_RED_1A2K_H0P8 1129.83,246.14 r90 top value=RED
LD3 "LED_yellow" LED_0603_OSRAM_LY-Q396-P1Q2-36_YELLOW_1A2K_H0P4 1059.83,246.14 r90 top value=YELLOW
LD4 "LED_green" LED_0603_OSRAM_LG-Q396-PS-35_GREEN_1A2K_H0P4 929.99,3845.01 r180 top value=GREEN
LD5 "LED_BICOLOR" LED_BI-GR_WE-150141SV73110 2804.88,3869.7 r180 top value="Green / Red"
LD6 "LED_BICOLOR" LED_BI-GR_WE-150141SV73110 2804.88,3579.69 r180 top value="Green / Red"
LNK1 "link_200" LINK200 2743.88,3040.7 r270 top
R1 "Resistor" R0402 454.87,1474.7 r270 top value=100R
R2 "Resistor" R0402 412.87,1315.3 r90 top value=4R7
R3 "Resistor" R0402 304.87,1659.7 r0 top value=10K
R4 "Resistor" R0402 304.87,1554.7 r180 top value=10K
R5 "Resistor" R0402 569.87,1594.7 r270 top value=30K
R6 "Resistor" R0402 619.87,1594.7 r270 top value=1K
R7 "Resistor" R0402 679.87,1689.7 r90 top value=1K
R8 "Resistor" R0402 715.66,2569.68 r270 top value=220R
R9 "Resistor" R0402 730.27,523.32 r90 top value=47R
R10 "Resistor" R0402 834.87,1774.69 r90 top value=220R
R11 "Resistor" R0402 729.87,1689.69 r270 top value=30K
R12 "Resistor" R0402 774.99,2065 r270 top value=10K
R13 "Resistor" R0402 834.98,1516.07 r90 top value=220R
R14 "Resistor" R0402 844.99,1660.01 r90 top value=220R
R15 "Resistor" R0402 924.99,3920.01 r0 top value=1K8
R16 "Resistor" R0402 944.99,1660.01 r90 top value=220R
R17 "Resistor" R0402 954.99,1170.01 r0 top value=30K
R18 "Resistor" R0402 954.99,1210.01 r180 top value=1K
R19 "Resistor" R0402 979.99,1505 r90 top value=220R
R20 "Resistor" R0402 1039.99,2830.01 r270 top value=220R
R21 "Resistor" R0402 1034.99,1660 r90 top value=220R
R22 "Resistor" R0402 1059.88,1329.7 r180 top value=30K
R23 "Resistor" R0402 1059.83,351.14 r90 top value=470R
R24 "Resistor" R0402 1079.87,1229.7 r90 top value=1K
R25 "Resistor" R0402 589.87,2574.7 r90 bottom value=220R
R26 "Resistor" R0402 1059.87,1169.7 r180 top value=30K
R27 "Resistor" R0402 1140,1210.01 r180 top value=1K
R28 "Resistor" R0402 1129.83,351.14 r90 top value=270R
R29 "Resistor" R0402 1139.83,1504.53 r90 top value=220R
R30 "Resistor" R0402 954.87,3584.69 r90 top value=100K
R31 "Resistor" R0402 1189.99,2800 r90 top value=10K
R32 "Resistor" R0402 1199.83,351.14 r90 top value=360R
R33 "Resistor" R0402 1219.88,1324.7 r180 top value=30K
R34 "Resistor" R0402 1189.87,3594.69 r90 top value=100K
R35 "Resistor" R0402 2579.87,3784.69 r270 top value=5K1
R36 "Resistor" R0402 1234.99,2545 r270 top value=100R
R37 "Resistor" R0402 1239.87,1224.7 r90 top value=1K
R38 "Resistor" R0402 1330.66,2546.3 r270 top value=0R
R39 "Resistor" R0402 1375.66,2546.3 r270 top value=0R
R40 "Resistor" R0402 1684.92,3897.68 r90 top value=33R
R41 "Resistor" R0402 1729.92,3897.66 r90 top value=0R
R42 "Resistor" R0402 1779.92,3897.67 r90 top value=0R
R43 "Resistor" R0402 1879.92,3900.4 r90 top value=0R
R44 "Resistor" R0402 1929.92,3900.4 r90 top value=33R
R45 "Resistor" R0402 1979.92,3900.4 r90 top value=33R
R46 "Resistor" R0402 2774.87,3444.69 r90 top value=330R
R47 "Resistor" R0402 2834.87,3444.7 r270 top value=1K
R48 "Resistor" R0402 2481.35,3579.12 r90 top value=3K
R49 "Resistor" R0402 1819.87,4139.7 r180 bottom value=100R
R50 "Resistor" R0402 2741.36,3235.3 r0 top value=5K1
R51 "Resistor" R0402 2741.35,3190.3 r0 top value=10K
R52 "Resistor" R0402 2741.35,3145.3 r0 top value=10K
R53 "Resistor" R0402 2741.36,3100.3 r0 top value=10K
R54 "Resistor" R0402 2579.87,3689.7 r90 top value=100K
R55 "Resistor" R0402 2624.87,3689.69 r90 top value=100K
R56 "Resistor" R0402 2624.87,3784.69 r270 top value=5K1
R57 "Resistor" R0402 2414.88,3199.7 r0 bottom value=10K
R58 "Resistor" R0402 2269.88,3909.7 r0 top value=3K
R59 "Resistor" R0402 2294.87,3839.7 r270 top value=5K1
R60 "Resistor" R0402 1838.49,2325.01 r0 bottom value=10K
R61 "Resistor" R0402 1444.88,2274.7 r180 bottom value=220R
R62 "Resistor" R0402 1419.87,1924.7 r90 bottom value=220R
R63 "Resistor" R0402 2059.87,3874.69 r270 top value=1K8
R64 "Resistor" R0402 2744.88,3374.7 r0 top value=0R
R65 "Resistor" R0402 1294.99,2275.01 r180 bottom value=220R
R66 "Resistor" R0402 1274.87,1924.7 r90 bottom value=220R
R67 "Resistor" R0402 1154.88,2274.7 r180 bottom value=220R
R68 "Resistor" R0402 1119.87,1924.7 r90 bottom value=220R
R69 "Resistor" R0402 745,2260 r0 bottom value=220R
R70 "Resistor" R0402 1164.87,2564.7 r270 bottom value=220R
R71 "Resistor" R0402 819.99,2580 r270 bottom value=220R
R72 "Resistor" R0402 1104.56,2694.58 r270 top value=220R
R73 "Resistor" R0402 620,2325.01 r0 bottom value=220R
R74 "Resistor" R0402 304.88,1739.7 r180 top value=0R
R75 "Resistor" R0402 499.88,1739.7 r0 top value=0R
R76 "Resistor" R0402 504.87,1474.7 r90 top value=0R
R77 "Resistor" R0402 434.88,1414.7 r180 top value=10K
R78 "Resistor" R0402 569.87,1689.7 r270 top value=30K
R79 "Resistor" R0402 774.87,1689.7 r270 top value=30K
R80 "Resistor" R0402 914.88,1259.7 r0 top value=30K
R81 "Resistor" R0402 1059.88,1289.7 r180 top value=30K
R82 "Resistor" R0402 1139.88,1169.7 r180 top value=30K
R83 "Resistor" R0402 1219.88,1284.7 r180 top value=30K
R84 "Resistor" R0402 2104.87,3874.7 r270 top value=1K3
R85 "Resistor" R0402 2324.87,3579.7 r90 top value=33R
R86 "Resistor" R0402 2159.87,3909.7 r90 top value=3K9
R87 "Resistor" R0402 2149.87,3719.7 r90 top value=100K
R88 "Resistor" R0402 2834.87,3729.7 r270 top value=1K
R89 "Resistor" R0402 2774.87,3729.7 r270 top value=330R
R90 "Resistor" R0402 2379.87,3579.7 r90 top value=100R
R91 "Resistor" R0402 1224.87,1924.7 r90 bottom value=0R
R92 "Resistor" R0402 1369.87,1924.7 r90 bottom value=0R
R93 "Resistor" R0402 1074.87,1924.7 r90 bottom value=0R
R94 "Resistor" R0402 764.87,2579.7 r270 bottom value=0R
R95 "Resistor" R0402 649.87,2569.7 r270 top value=0R
R96 "Resistor" R0402 994.87,2829.7 r270 top value=0R
R97 "Resistor" R0402 1224.88,2274.7 r0 bottom value=0R
R98 "Resistor" R0402 1369.88,2274.7 r0 bottom value=0R
R99 "Resistor" R0402 1084.88,2274.7 r0 bottom value=0R
RV1 "POTENTIOMETER" POT_BOURNS_3386P-1-101TLF 695.27,278.32 r0 top value=10K
SB1 "SB_ON" SOLDER-BRIDGE_R0603-0R 499.87,1624.7 r270 top
SB2 "SB_ON" SOLDER-BRIDGE_R0603-0R 434.99,1130.01 r90 top
SB3 "SB_ON" SOLDER-BRIDGE_R0603-0R 499.99,1130.01 r90 top
SB4 "SB_ON" SOLDER-BRIDGE_R0603-0R 539.99,2700.01 r270 top
SB5 "SB_ON" SOLDER-BRIDGE_R0603-0R 606.06,1866.54 r180 top
SB6 "SB_ON" SOLDER-BRIDGE_R0603-0R 609.99,1931.07 r180 top
SB7 "SB_ON" SOLDER-BRIDGE_R0603-0R 609.99,2381.07 r180 top
SB8 "SB_ON" SOLDER-BRIDGE_R0603-0R 610.31,1993.95 r180 top
SB9 "SB_OFF" SOLDER-BRIDGE_R0603-0R 594.99,2700.01 r270 top
SB10 "SB_OFF" SOLDER-BRIDGE_R0603-0R 649.99,2700.01 r270 top
SB11 "SB_ON" SOLDER-BRIDGE_R0603-0R 669.99,1585.02 r90 top
SB12 "SB_ON" SOLDER-BRIDGE_R0603-0R 725,3670.01 r180 top
SB13 "SB_ON" SOLDER-BRIDGE_R0603-0R 741.07,1866.06 r180 top
SB14 "SB_ON" SOLDER-BRIDGE_R0603-0R 1107,2568 r90 top
SB15 "SB_ON" SOLDER-BRIDGE_R0603-0R 744.99,2325.01 r180 top
SB16 "SB_ON" SOLDER-BRIDGE_R0603-0R 744.99,1993.95 r180 top
SB17 "SB_ON" SOLDER-BRIDGE_R0603-0R 745,2380.01 r180 top
SB18 "SB_ON" SOLDER-BRIDGE_R0603-0R 745.84,1930.86 r180 top
SB19 "SB_OFF" SOLDER-BRIDGE_R0603-0R 719.83,2699.69 r270 top
SB20 "SB_OFF" SOLDER-BRIDGE_R0603-0R 719.83,2849.37 r90 top
SB21 "SB_OFF" SOLDER-BRIDGE_R0603-0R 756.21,1555 r0 top
SB22 "SB_ON" SOLDER-BRIDGE_R0603-0R 756.21,1615 r0 top
SB23 "SB_ON" SOLDER-BRIDGE_R0603-0R 776.84,2698.86 r270 top
SB24 "SB_OFF" SOLDER-BRIDGE_R0603-0R 784.83,2849.37 r90 top
SB25 "SB_OFF" SOLDER-BRIDGE_R0603-0R 829.84,2699.86 r270 top
SB26 "SB_ON" SOLDER-BRIDGE_R0603-0R 866.37,520 r0 top
SB27 "SB_ON" SOLDER-BRIDGE_R0603-0R 844.83,2849.69 r90 top
SB28 "SB_ON" SOLDER-BRIDGE_R0603-0R 924.87,2569.7 r90 top
SB29 "SB_ON" SOLDER-BRIDGE_R0603-0R 869.87,2569.7 r90 top
SB30 "SB_ON" SOLDER-BRIDGE_R0603-0R 980,2570 r90 top
SB31 "SB_OFF" SOLDER-BRIDGE_R0603-0R 979.71,1401.39 r90 top
SB32 "SB_ON" SOLDER-BRIDGE_R0603-0R 979.99,1290 r270 top
SB33 "SB_ON" SOLDER-BRIDGE_R0603-0R 1039.99,2710.02 r90 top
SB34 "SB_ON" SOLDER-BRIDGE_R0603-0R 1034.99,2570.02 r90 top
SB35 "SB_ON" SOLDER-BRIDGE_R0603-0R 1039.71,1401.39 r90 top
SB36 "SB_ON" SOLDER-BRIDGE_R0603-0R 649.87,2579.7 r90 bottom
SB37 "SB_OFF" SOLDER-BRIDGE_R0603-0R 1149.83,1401.07 r90 top
SB38 "SB_ON" SOLDER-BRIDGE_R0603-0R 1149.99,1290.01 r270 top
SB39 "SB_ON" SOLDER-BRIDGE_R0603-0R 1204.83,1401.07 r90 top
SB40 "SB_ON" SOLDER-BRIDGE_R0603-0R 1434.99,1660.01 r270 top
SB41 "SB_ON" SOLDER-BRIDGE_R0603-0R 1464.99,2560.01 r90 top
SB42 "SB_ON" SOLDER-BRIDGE_R0603-0R 1514.99,1560.01 r0 top
SB43 "SB_ON" SOLDER-BRIDGE_R0603-0R 1489.99,1660 r270 top
SB44 "SB_ON" SOLDER-BRIDGE_R0603-0R 1519.99,2560.01 r90 top
SB45 "SB_ON" SOLDER-BRIDGE_R0603-0R 1544.99,1660 r270 top
SB46 "SB_ON" SOLDER-BRIDGE_R0603-0R 1599.99,1660 r270 top
SB47 "SB_ON" SOLDER-BRIDGE_R0603-0R 1678.49,2240 r0 top
SB48 "SB_ON" SOLDER-BRIDGE_R0603-0R 1678.49,2325 r0 top
SB49 "SB_OFF" SOLDER-BRIDGE_R0603-0R 1679.99,2160.01 r0 top
SB50 "SB_ON" SOLDER-BRIDGE_R0603-0R 1680,2385.01 r180 top
SB51 "SB_ON" SOLDER-BRIDGE_R0603-0R 1683.61,1994.69 r0 top
SB52 "SB_ON" SOLDER-BRIDGE_R0603-0R 1684.99,2070.01 r0 top
SB53 "SB_ON" SOLDER-BRIDGE_R0603-0R 1687.24,1840.33 r0 top
SB54 "SB_OFF" SOLDER-BRIDGE_R0603-0R 1836.05,1995.01 r180 top
SB55 "SB_ON" SOLDER-BRIDGE_R0603-0R 1838.49,2325 r0 top
SB56 "SB_OFF" SOLDER-BRIDGE_R0603-0R 1838.8,2235 r0 top
SB57 "SB_OFF" SOLDER-BRIDGE_R0603-0R 1840,2385.01 r180 top
SB58 "SB_ON" SOLDER-BRIDGE_R0603-0R 1840,2160.01 r0 top
SB59 "SB_ON" SOLDER-BRIDGE_R0603-0R 1847.71,2069.69 r0 top
SB60 "SB_ON" SOLDER-BRIDGE_R0603-0R 1974.99,1995.01 r0 top
SB61 "SB_OFF" SOLDER-BRIDGE_R0603-0R 219.87,2434.7 r90 top
SB62 "SB_ON" SOLDER-BRIDGE_R0603-0R 330,3013.32 r270 top
SB63 "SB_OFF" SOLDER-BRIDGE_R0603-0R 389.87,3014.78 r270 top
SB64 "SB_OFF" SOLDER-BRIDGE_R0603-0R 269.87,3014.77 r270 top
SB65 "SB_ON" SOLDER-BRIDGE_R0603-0R 214.87,3014.78 r270 top
SB66 "SB_ON" SOLDER-BRIDGE_R0603-0R 1847.71,2069.68 r0 bottom
SB67 "SB_ON" SOLDER-BRIDGE_R0603-0R 1840,2160.01 r0 bottom
SB68 "SB_ON" SOLDER-BRIDGE_R0603-0R 1838.8,2235 r0 bottom
SB69 "SB_ON" SOLDER-BRIDGE_R0603-0R 1687.24,1840.33 r0 bottom
SB70 "SB_ON" SOLDER-BRIDGE_R0603-0R 1684.99,2070.01 r0 bottom
SB71 "SB_ON" SOLDER-BRIDGE_R0603-0R 1683.93,2160.01 r0 bottom
SB72 "SB_ON" SOLDER-BRIDGE_R0603-0R 1678.49,2240 r0 bottom
SB73 "SB_OFF" SOLDER-BRIDGE_R0603-0R 1399.99,2105 r180 bottom
SB74 "SB_ON" SOLDER-BRIDGE_R0603-0R 1399.99,2160 r180 bottom
SB75 "SB_ON" SOLDER-BRIDGE_R0603-0R 1396.05,2050 r180 bottom
SB76 "SB_ON" SOLDER-BRIDGE_R0603-0R 1251.53,2045.75 r180 bottom
SB77 "SB_OFF" SOLDER-BRIDGE_R0603-0R 1251.53,2100.75 r180 bottom
SB78 "SB_ON" SOLDER-BRIDGE_R0603-0R 1251.53,2155.75 r180 bottom
SB79 "SB_ON" SOLDER-BRIDGE_R0603-0R 1112.24,2156.07 r180 bottom
SB80 "SB_OFF" SOLDER-BRIDGE_R0603-0R 1110.86,2101.06 r180 bottom
SB81 "SB_ON" SOLDER-BRIDGE_R0603-0R 1110.74,2040.75 r180 bottom
SB82 "SB_ON" SOLDER-BRIDGE_R0603-0R 714.87,2579.7 r90 bottom
SB83 "SB_ON" SOLDER-BRIDGE_R0603-0R 779.99,2155.01 r90 bottom
SB84 "SB_ON" SOLDER-BRIDGE_R0603-0R 745.84,1930.86 r180 bottom
SB85 "SB_ON" SOLDER-BRIDGE_R0603-0R 744.99,1993.95 r180 bottom
SB86 "SB_ON" SOLDER-BRIDGE_R0603-0R 1106.24,2569.59 r90 bottom
SB87 "SB_ON" SOLDER-BRIDGE_R0603-0R 744.99,2325.01 r180 bottom
SB88 "SB_ON" SOLDER-BRIDGE_R0603-0R 741.05,1866.07 r180 bottom
SB89 "SB_ON" SOLDER-BRIDGE_R0603-0R 610.3,1993.94 r180 bottom
SB90 "SB_ON" SOLDER-BRIDGE_R0603-0R 609.99,1931.07 r180 bottom
SB91 "SB_ON" SOLDER-BRIDGE_R0603-0R 609.99,2381.06 r180 bottom
SB92 "SB_ON" SOLDER-BRIDGE_R0603-0R 606.06,1866.54 r180 bottom
TP1 "Test Point" TP_SMD_1MM 359.99,3925 r90 top
TP2 "Test Point" TP_SMD_1MM 624.87,1479.7 r90 top
TP3 "Test Point" TP_SMD_1MM 494.99,3920.01 r0 top
TP4 "Test Point" TP_SMD_1MM 609.99,3670.01 r0 top
TP5 "Test Point" TP_SMD_1MM 1549.99,1170.01 r90 top
TP6 "Test Point" TP_SMD_1MM 1854.99,1220.01 r90 top
TP7 "Test Point" TP_SMD_1MM 1979.99,1220.01 r90 top
TP8 "Test Point" TP_SMD_1MM 2029.99,1330.01 r90 top
TP9 "Test Point" TP_SMD_1MM 2074.99,1780.01 r90 top
TP10 "Test Point" TP_SMD_1MM 2109.99,1070.01 r90 top
TP11 "Test Point" TP_SMD_1MM 2109.99,1170.01 r90 top
TP12 "Test Point" TP_SMD_1MM 2329.99,950.01 r90 top
TP13 "Test Point" TP_SMD_1MM 2329.99,1070.01 r90 top
TP14 "Test Point" TP_SMD_1MM 2409.99,1360.01 r90 top
TP15 "Test Point" TP_SMD_1MM 2414.99,1170.01 r90 top
TP16 "Test Point" TP_SMD_1MM 2434.99,1500.01 r90 top
TP17 "Test Point" TP_SMD_1MM 2439.99,1720.01 r90 top
TP18 "Test Point" TP_SMD_1MM 2509.99,2320.01 r180 top
TP19 "Test Point" TP_SMD_1MM 2549.99,1120.01 r90 top
TP20 "Test Point" TP_SMD_1MM 2554.99,675 r90 top
TP21 "Test Point" TP_SMD_1MM 2554.99,850 r270 top
TP22 "Test Point" TP_SMD_1MM 2554.99,1000.01 r90 top
TP23 "Test Point" TP_SMD_1MM 2554.99,1965.01 r90 top
TP24 "Test Point" TP_SMD_1MM 2554.99,2425.01 r180 top
TP25 "Test Point" TP_SMD_1MM 2554.99,2530.01 r180 top
TP26 "Test Point" TP_SMD_1MM 2554.99,2650.01 r90 top
TP27 "Test Point" TP_SMD_1MM 2554.99,2770.01 r180 top
TP28 "Test Point" TP_SMD_1MM 2554.99,2890.01 r180 top
TP29 "Test Point" TP_SMD_1MM 2559.99,560.01 r90 top
TP30 "Test Point" TP_SMD_1MM 2619.99,1620.01 r90 top
TP31 "Test Point" TP_SMD_1MM 2679.99,600 r90 top
TP32 "Test Point" TP_SMD_1MM 2679.99,775 r90 top
TP33 "Test Point" TP_SMD_1MM 2679.99,950 r90 top
TP34 "Test Point" TP_SMD_1MM 2679.99,2355.01 r180 top
TP35 "Test Point" TP_SMD_1MM 2679.99,2480.01 r180 top
TP36 "Test Point" TP_SMD_1MM 2679.99,2580.01 r180 top
TP37 "Test Point" TP_SMD_1MM 2679.99,2700.01 r90 top
TP38 "Test Point" TP_SMD_1MM 2679.99,2845.01 r180 top
TP39 "Test Point" TP_SMD_1MM 2684.99,1145.01 r90 top
TP40 "Test Point" TP_SMD_1MM 2684.99,1350.01 r90 top
TP41 "Test Point" TP_SMD_1MM 2684.99,1965.01 r90 top
TP42 "Test Point" TP_SMD_1MM 2909.99,3210.01 r180 top
TP43 "Test Point" TP_SMD_1MM 2394.87,3649.7 r90 top
U1 "TS461CLT" AOP_SOT23-5L_H1P45 322.88,1454.99 r180 top
U2 "LDL112PV33R" ICC_DFN6-EPAD_3X3_P095 724.99,3805.01 r270 top
U3 "ESD-TRANSIL" ESD_ST0201 685.27,523.32 r90 top value=ESDALC6V1-1U2
U4 "STG4160" ESD_FLIP-CHIP-BGA8_1P9X0P9_P050 714.99,2070.01 r270 top
U5 "STM32G473QET6" ICC_LQFP128_14X14_P040 1224.99,2089.7 r270 top
U6 "STMPS2151STR" MOS_SOT23-5L 1077.12,3648.94 r270 top
U7 "ESD-TRANSIL" ESD_ST0201 1384.99,335 r180 top value=ESDALC6V1-1U2
U8 "ST730M33R" ICC_SOT23-5L_H1P45 1499.88,3634.7 r180 top
U9 "ESDALC6V1W5" ESD_SOT323-5L 1714.86,3774.7 r270 top
U10 "ESDALC6V1W5" ESD_SOT323-5L 1909.86,3774.7 r270 top
U11 "ESD-TRANSIL" ESD_ST0201 2069.99,340 r180 top value=ESDALC6V1-1U2
U12 "STLINK-V3EC" ICC_UFBGA201_176+25_10X10_P065 2465.18,3294.12 r90 top value=STM32F723IEK6
U13 "ESD-TRANSIL" ESD_QFN1610_2N_1K_2A 2394.88,3749.7 r180 top value=ESDA25P35-1U1M
U14 "ECMF02-2AMX6" ESD_QFN-6L_1P7X1P5_P050 2488.86,3764.7 r180 top
U15 "TPS259535DSG" ICC_WSON8-EPAD_2X2_P050 2169.88,3814.7 r90 top
X1 "OSCILLATOR_4_PINS" CRY_NZ2016SH_4P 1214.98,2680 r270 top value=24MHz
X2 "XTAL_2_PINS" CRY_NX2012SA_2P 1356.72,2711.29 r0 top value=32.768KHz
X3 "XTAL_4_PINS" CRY_NX2016SA_4P 2439.86,2959.7 r0 top value=24MHz

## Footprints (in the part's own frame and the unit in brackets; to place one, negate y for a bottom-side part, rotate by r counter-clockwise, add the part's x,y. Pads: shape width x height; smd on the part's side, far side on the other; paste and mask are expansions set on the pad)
AOP_SOT23-5L_H1P45 [mm]
  rect 0.6x1.3 smd mask+0.05: 1(-0.95,-1.1) 2(0,-1.1) 3(0.95,-1.1) 4(0.95,1.1) 5(-0.95,1.1)
  silkscreen extent -1.75,-1.68 1.6,0.97, body extent -1.52,-1.25 1.52,1.25, height 1.45
C0402 [mm]
  rect 0.51x0.56 smd mask+0.05: 1(-0.45,0) 2(0.45,0)
  body extent -0.5,-0.3 0.5,0.3, height 0.4
C0603 [mm]
  rect 0.64x0.89 smd mask+0.05: 1(-0.7,0) 2(0.7,0)
  silkscreen extent -1.05,-0.55 1.02,0.55, body extent -0.9,-0.5 0.9,0.5, height 1.4
C0603_H0P8 [mm] "MCD-01540"
  rect 0.64x0.89 smd mask+0.05: 1(-0.7,0) 2(0.7,0)
  silkscreen extent -0.9,-0.55 0.9,0.55, body extent -0.9,-0.5 0.9,0.5, height 1
C0805 [mm]
  rect 0.9x1.4 smd mask+0.05: 1(-0.85,0) 2(0.85,0)
  silkscreen extent -1.3,-0.77 1.3,0.77, body extent -1.1,-0.7 1.1,0.7, height 1.35
CON_BOARD_GOLDFINGER_PCI_EXPRESS_X16 [mm] "MCD-02436"
  rect 0.7x3.2 smd far side paste-1 mask+0.05: A01(-11.5,0.355)
  rect 0.7x3.91 smd far side paste-1 mask+0.05: A02(-10.5,0) A03(-9.5,0) A04(-8.5,0) A05(-7.5,0) A06(-6.5,0) A07(-5.5,0) A08(-4.5,0) A09(-3.5,0) A10(-2.5,0) A11(-1.5,0) A12(1.5,0) A13(2.5,0) A14(3.5,0) A15(4.5,0) A16(5.5,0) A17(6.5,0) A18(7.5,0) A19(8.5,0) A20(9.5,0) A21(10.5,0) A22(11.5,0) A23(12.5,0) A24(13.5,0) A25(14.5,0) A26(15.5,0) A27(16.5,0) A28(17.5,0) A29(18.5,0) A30(19.5,0) A31(20.5,0) A32(21.5,0) A33(22.5,0) A34(23.5,0) A35(24.5,0) A36(25.5,0) A37(26.5,0) A38(27.5,0) A39(28.5,0) A40(29.5,0) A41(30.5,0) A42(31.5,0) A43(32.5,0) A44(33.5,0) A45(34.5,0) A46(35.5,0) A47(36.5,0) A48(37.5,0) A49(38.5,0) A50(39.5,0) A51(40.5,0) A52(41.5,0) A53(42.5,0) A54(43.5,0) A55(44.5,0) A56(45.5,0) A57(46.5,0) A58(47.5,0) A59(48.5,0) A60(49.5,0) A61(50.5,0) A62(51.5,0) A63(52.5,0) A64(53.5,0) A65(54.5,0) A66(55.5,0) A67(56.5,0) A68(57.5,0) A69(58.5,0) A70(59.5,0) A71(60.5,0) A72(61.5,0) A73(62.5,0) A74(63.5,0) A75(64.5,0) A76(65.5,0) A77(66.5,0) A78(67.5,0) A79(68.5,0) A80(69.5,0) A81(70.5,0) A82(71.5,0)
  rect 0.7x3.91 smd paste-1 mask+0.05: B01(-11.5,0) B02(-10.5,0) B03(-9.5,0) B04(-8.5,0) B05(-7.5,0) B06(-6.5,0) B07(-5.5,0) B08(-4.5,0) B09(-3.5,0) B10(-2.5,0) B11(-1.5,0) B12(1.5,0) B13(2.5,0) B14(3.5,0) B15(4.5,0) B16(5.5,0) B18(7.5,0) B19(8.5,0) B20(9.5,0) B21(10.5,0) B22(11.5,0) B23(12.5,0) B24(13.5,0) B25(14.5,0) B26(15.5,0) B27(16.5,0) B28(17.5,0) B29(18.5,0) B30(19.5,0) B32(21.5,0) B33(22.5,0) B34(23.5,0) B35(24.5,0) B36(25.5,0) B37(26.5,0) B38(27.5,0) B39(28.5,0) B40(29.5,0) B41(30.5,0) B42(31.5,0) B43(32.5,0) B44(33.5,0) B45(34.5,0) B46(35.5,0) B47(36.5,0) B49(38.5,0) B50(39.5,0) B51(40.5,0) B52(41.5,0) B53(42.5,0) B54(43.5,0) B55(44.5,0) B56(45.5,0) B57(46.5,0) B58(47.5,0) B59(48.5,0) B60(49.5,0) B61(50.5,0) B62(51.5,0) B63(52.5,0) B64(53.5,0) B65(54.5,0) B66(55.5,0) B67(56.5,0) B68(57.5,0) B69(58.5,0) B70(59.5,0) B71(60.5,0) B72(61.5,0) B73(62.5,0) B74(63.5,0) B75(64.5,0) B76(65.5,0) B77(66.5,0) B78(67.5,0) B79(68.5,0) B80(69.5,0) B82(71.5,0)
  rect 0.7x3.2 smd paste-1 mask+0.05: B17(6.5,0.355) B31(20.5,0.355) B48(37.5,0.355) B81(70.5,0.355)
  silkscreen extent -12.15,-3.64 72.15,4.76
CON_SAMTEC_FTSH-105-01-L-DV-K [mm]
  oval 0.74x2.79 smd mask+0.05: 1(-2.54,-2.035) 2(-2.54,2.035) 3(-1.27,-2.035) 4(-1.27,2.035) 5(0,-2.035) 6(0,2.035) 7(1.27,-2.035) 8(1.27,2.035) 9(2.54,-2.035) 10(2.54,2.035)
  round 0 hole 1 unplated paste-10 mask+0.05: NPTH1(-1.905,0) NPTH2(1.905,0)
  silkscreen extent -3.18,-2.54 3.18,2.54, body extent -3.18,-2.92 3.18,2.92, height 6.12
CON_SAMTEC_FTSH-107-01-L-DV-K-A [mm] "MCD-01959"
  oval 0.74x2.79 smd mask+0.05: 1(-3.81,-2.035) 2(-3.81,2.035) 3(-2.54,-2.035) 4(-2.54,2.035) 5(-1.27,-2.035) 6(-1.27,2.035) 7(0,-2.035) 8(0,2.035) 9(1.27,-2.035) 10(1.27,2.035) 11(2.54,-2.035) 12(2.54,2.035) 13(3.81,-2.035) 14(3.81,2.035)
  round 0 hole 1 unplated paste-10 mask+0.05: NPTH1(-3.175,0) NPTH2(3.175,0)
  silkscreen extent -4.44,-2.54 4.44,2.54, body extent -4.44,-2.92 4.45,2.92, height 6.12
CON_SAMTEC_TSW-102-07-G-S [mm]
  rect 1.85x1.85 / inner round 1.85 / far side rect 1.85x1.85 hole 1 mask+0.05: 1(-1.27,0)
  round 1.85 hole 1 mask+0.05: 2(1.27,0)
  silkscreen extent -2.58,-1.3 2.58,1.3, body extent -2.67,-1.3 2.58,1.3, height 8.38
CON_SAMTEC_TSW-103-07-F-S [mm]
  rect 1.85x1.85 / inner round 1.85 / far side rect 1.85x1.85 hole 1 mask+0.05: 1(-2.54,0)
  round 1.85 hole 1 mask+0.05: 2(0,0) 3(2.54,0)
  silkscreen extent -3.85,-1.3 3.85,1.3, body extent -3.94,-1.37 3.91,1.37, height 8.38
CON_SAMTEC_TSW-104-07-G-S [mm]
  rect 1.85x1.85 / inner round 1.85 / far side rect 1.85x1.85 hole 1 mask+0.05: 1(-3.81,0)
  round 1.85 hole 1 mask+0.05: 2(-1.27,0) 3(1.27,0) 4(3.81,0)
  silkscreen extent -5.12,-1.3 5.12,1.3, body extent -5.21,-1.37 5.18,1.37, height 8.38
CON_SAMTEC_TSW-104-07-X-D [mm]
  rect 1.85x1.85 / inner round 1.85 / far side rect 1.85x1.85 hole 1 mask+0.05: 1(-3.81,-1.27)
  round 1.85 hole 1 mask+0.05: 2(-3.81,1.27) 3(-1.27,-1.27) 4(-1.27,1.27) 5(1.27,-1.27) 6(1.27,1.27) 7(3.81,-1.27) 8(3.81,1.27)
  silkscreen extent -5.08,-2.54 5.08,2.54, body extent -5.08,-2.54 5.08,2.54, height 8.38
CON_SAMTEC_TSW-119-09-X-D [mm]
  rect 1.85x1.85 / inner round 1.85 / far side rect 1.85x1.85 hole 1 mask+0.05: 1(-22.86,-1.27)
  round 1.85 hole 1 mask+0.05: 2(-22.86,1.27) 3(-20.32,-1.27) 4(-20.32,1.27) 5(-17.78,-1.27) 6(-17.78,1.27) 7(-15.24,-1.27) 8(-15.24,1.27) 9(-12.7,-1.27) 10(-12.7,1.27) 11(-10.16,-1.27) 12(-10.16,1.27) 13(-7.62,-1.27) 14(-7.62,1.27) 15(-5.08,-1.27) 16(-5.08,1.27) 17(-2.54,-1.27) 18(-2.54,1.27) 19(0,-1.27) 20(0,1.27) 21(2.54,-1.27) 22(2.54,1.27) 23(5.08,-1.27) 24(5.08,1.27) 25(7.62,-1.27) 26(7.62,1.27) 27(10.16,-1.27) 28(10.16,1.27) 29(12.7,-1.27) 30(12.7,1.27) 31(15.24,-1.27) 32(15.24,1.27) 33(17.78,-1.27) 34(17.78,1.27) 35(20.32,-1.27) 36(20.32,1.27) 37(22.86,-1.27) 38(22.86,1.27)
  silkscreen extent -24.13,-2.54 24.13,2.54, body extent -24.13,-2.55 24.13,2.54, height 8.38
CON_USB-TYPEC_COXOC_317JD24BZTF3K3C3 [mm]
  rect 0.3x1.2 smd mask+0.05: A1(-2.75,10.58) A2(-2.25,10.58) A3(-1.75,10.58) A4(-1.25,10.58) A5(-0.75,10.58) A6(-0.25,10.58) A7(0.25,10.58) A8(0.75,10.58) A9(1.25,10.58) A10(1.75,10.58) A11(2.25,10.58) A12(2.75,10.58)
  round 0.6 hole 0.4 mask+0.05: B1(2,9.33) B1(2.8,9.33) B2(2.4,8.62) B3(1.6,8.62) B4(1.2,9.33) B5(0.8,8.62) B6(0.4,9.33) B7(-0.4,9.33) B8(-0.8,8.62) B9(-1.2,9.33) B10(-1.6,8.62) B11(-2.4,8.62) B12(-2.8,9.33) B12(-2,9.33)
  oval 1.15x1.55 hole 0.45 slot 0.85 at 90 deg mask+0.05: SH1(-4.27,8.18) SH2(-4.27,3.45) SH3(4.27,8.18) SH4(4.27,3.45)
  silkscreen extent -4.38,-0.95 4.38,10.38, body extent -4.38,-0.95 4.38,10.84, height 3.03
CRY_NX2012SA_2P [mm]
  rect 1x1.25 smd mask+0.05: 1(-0.75,0) 2(0.75,0)
  silkscreen extent -1.05,-0.75 1.05,0.75, body extent -1.05,-0.63 1.05,0.63, height 0.6
CRY_NX2016SA_4P [mm]
  rect 0.85x0.75 smd mask+0.05: 1(-0.675,-0.525) 2(0.675,-0.525) 3(0.675,0.525) 4(-0.675,0.525)
  silkscreen extent -1.22,-1.02 1.05,0.85, body extent -1.05,-0.85 1.05,0.85, height 0.7
CRY_NZ2016SH_4P [mm] "MCD-01627"
  rect 0.8x0.7 smd mask+0.05: 1(-0.65,-0.5) 2(0.65,-0.5) 3(0.65,0.5) 4(-0.65,0.5)
  silkscreen extent -1.17,-0.97 1.05,0.85, body extent -1.05,-0.85 1.05,0.85, height 0.71
DIO_SOD323_1A_2K [mm]
  rect 1.06x0.54 smd mask+0.05: 1(-1.07,0) 2(1.07,0)
  silkscreen extent -0.9,-0.72 0.9,0.72, body extent -1.3,-0.78 1.3,0.78, height 1.17
DIO_SOD523_1A_2K [mm] "MCD-01677"
  rect 0.65x0.3 smd mask+0.05: 1(-0.675,0) 2(0.675,0)
  silkscreen extent -0.65,-0.45 1.05,0.55, body extent -0.85,-0.45 0.85,0.45, height 0.71
ESD_FLIP-CHIP-BGA8_1P9X0P9_P050 [mm] "IPC"
  round 0.2 smd paste+0 mask+0.05: 1(-0.75,-0.25) 2(-0.25,-0.25) 3(0.25,-0.25) 4(0.75,-0.25) 5(0.75,0.25) 6(0.25,0.25) 7(-0.25,0.25) 8(-0.75,0.25)
  silkscreen extent -1.17,-0.67 1.02,0.53, body extent -0.97,-0.48 0.97,0.48, height 0.64
ESD_QFN1610_2N_1K_2A [mm] "DFN, 2-Leads, Body 1.60x1.00mm"
  rect 0.55x0.9 smd mask+0.05: 1(-0.625,0) 2(0.625,0)
  silkscreen extent -1.02,-0.58 0.85,0.58, body extent -0.85,-0.55 0.85,0.55, height 0.6
ESD_QFN-6L_1P7X1P5_P050 [mm]
  rect 0.25x0.6 smd mask+0.05: 1(-0.5,-0.65) 2(0,-0.65) 3(0.5,-0.65) 4(0.5,0.65) 5(0,0.65) 6(-0.5,0.65)
  silkscreen extent -0.9,-0.8 0.9,0.8, body extent -0.9,-0.8 0.9,0.8, height 0.56
ESD_SOT323-5L [mm]
  rect 0.4x1.2 smd mask+0.05: 1(-0.65,-0.85) 2(0,-0.85) 3(0.65,-0.85) 4(0.65,0.85) 5(-0.65,0.85)
  silkscreen extent -1.22,-1.21 1.22,0.77, body extent -1.15,-1.05 1.15,1.05, height 1.1
ESD_ST0201 [mm]
  rect 0.425x0.33 smd mask+0.05: 1(-0.312,0) 2(0.312,0)
  silkscreen extent -0.55,-0.3 0.33,0.3, body extent -0.34,-0.18 0.34,0.18, height 0.34
ICC_DFN6-EPAD_3X3_P095 [mm]
  rect 0.45x0.5 smd mask+0.05: 1(-0.95,-1.3) 2(0,-1.3) 3(0.95,-1.3) 4(0.95,1.3) 5(0,1.3) 6(-0.95,1.3)
  rect 2.5x1.7 smd mask+0.05: EP(0,0)
  silkscreen extent -1.55,-1.55 1.55,1.55, body extent -1.55,-1.55 1.55,1.55, height 1
ICC_LQFP128_14X14_P040 [mm]
  rect 1.78x0.225 smd mask+0.038: 1(-7.62,6.2) 2(-7.62,5.8) 3(-7.62,5.4) 4(-7.62,5) 5(-7.62,4.6) 6(-7.62,4.2) 7(-7.62,3.8) 8(-7.62,3.4) 9(-7.62,3) 10(-7.62,2.6) 11(-7.62,2.2) 12(-7.62,1.8) 13(-7.62,1.4) 14(-7.62,1) 15(-7.62,0.6) 16(-7.62,0.2) 17(-7.62,-0.2) 18(-7.62,-0.6) 19(-7.62,-1) 20(-7.62,-1.4) 21(-7.62,-1.8) 22(-7.62,-2.2) 23(-7.62,-2.6) 24(-7.62,-3) 25(-7.62,-3.4) 26(-7.62,-3.8) 27(-7.62,-4.2) 28(-7.62,-4.6) 29(-7.62,-5) 30(-7.62,-5.4) 31(-7.62,-5.8) 32(-7.62,-6.2) 65(7.62,-6.2) 66(7.62,-5.8) 67(7.62,-5.4) 68(7.62,-5) 69(7.62,-4.6) 70(7.62,-4.2) 71(7.62,-3.8) 72(7.62,-3.4) 73(7.62,-3) 74(7.62,-2.6) 75(7.62,-2.2) 76(7.62,-1.8) 77(7.62,-1.4) 78(7.62,-1) 79(7.62,-0.6) 80(7.62,-0.2) 81(7.62,0.2) 82(7.62,0.6) 83(7.62,1) 84(7.62,1.4) 85(7.62,1.8) 86(7.62,2.2) 87(7.62,2.6) 88(7.62,3) 89(7.62,3.4) 90(7.62,3.8) 91(7.62,4.2) 92(7.62,4.6) 93(7.62,5) 94(7.62,5.4) 95(7.62,5.8) 96(7.62,6.2)
  rect 0.225x1.78 smd mask+0.038: 33(-6.2,-7.62) 34(-5.8,-7.62) 35(-5.4,-7.62) 36(-5,-7.62) 37(-4.6,-7.62) 38(-4.2,-7.62) 39(-3.8,-7.62) 40(-3.4,-7.62) 41(-3,-7.62) 42(-2.6,-7.62) 43(-2.2,-7.62) 44(-1.8,-7.62) 45(-1.4,-7.62) 46(-1,-7.62) 47(-0.6,-7.62) 48(-0.2,-7.62) 49(0.2,-7.62) 50(0.6,-7.62) 51(1,-7.62) 52(1.4,-7.62) 53(1.8,-7.62) 54(2.2,-7.62) 55(2.6,-7.62) 56(3,-7.62) 57(3.4,-7.62) 58(3.8,-7.62) 59(4.2,-7.62) 60(4.6,-7.62) 61(5,-7.62) 62(5.4,-7.62) 63(5.8,-7.62) 64(6.2,-7.62) 97(6.2,7.62) 98(5.8,7.62) 99(5.4,7.62) 100(5,7.62) 101(4.6,7.62) 102(4.2,7.62) 103(3.8,7.62) 104(3.4,7.62) 105(3,7.62) 106(2.6,7.62) 107(2.2,7.62) 108(1.8,7.62) 109(1.4,7.62) 110(1,7.62) 111(0.6,7.62) 112(0.2,7.62) 113(-0.2,7.62) 114(-0.6,7.62) 115(-1,7.62) 116(-1.4,7.62) 117(-1.8,7.62) 118(-2.2,7.62) 119(-2.6,7.62) 120(-3,7.62) 121(-3.4,7.62) 122(-3.8,7.62) 123(-4.2,7.62) 124(-4.6,7.62) 125(-5,7.62) 126(-5.4,7.62) 127(-5.8,7.62) 128(-6.2,7.62)
  silkscreen extent -7.1,-7.1 7.1,7.1, body extent -8,-8 8,8, height 1.61
ICC_SOT23-5L_H1P45 [mm]
  rect 0.6x1.3 smd mask+0.05: 1(-0.95,-1.1) 2(0,-1.1) 3(0.95,-1.1) 4(0.95,1.1) 5(-0.95,1.1)
  silkscreen extent -1.75,-1.68 1.6,0.97, body extent -1.52,-1.25 1.52,1.25, height 1.45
